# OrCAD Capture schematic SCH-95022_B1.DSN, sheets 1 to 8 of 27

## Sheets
1 Page01 COVER: title: FRDM-IMX8MPLUS; rev: B1; note: SCH-95022 PDF: SPF-95022
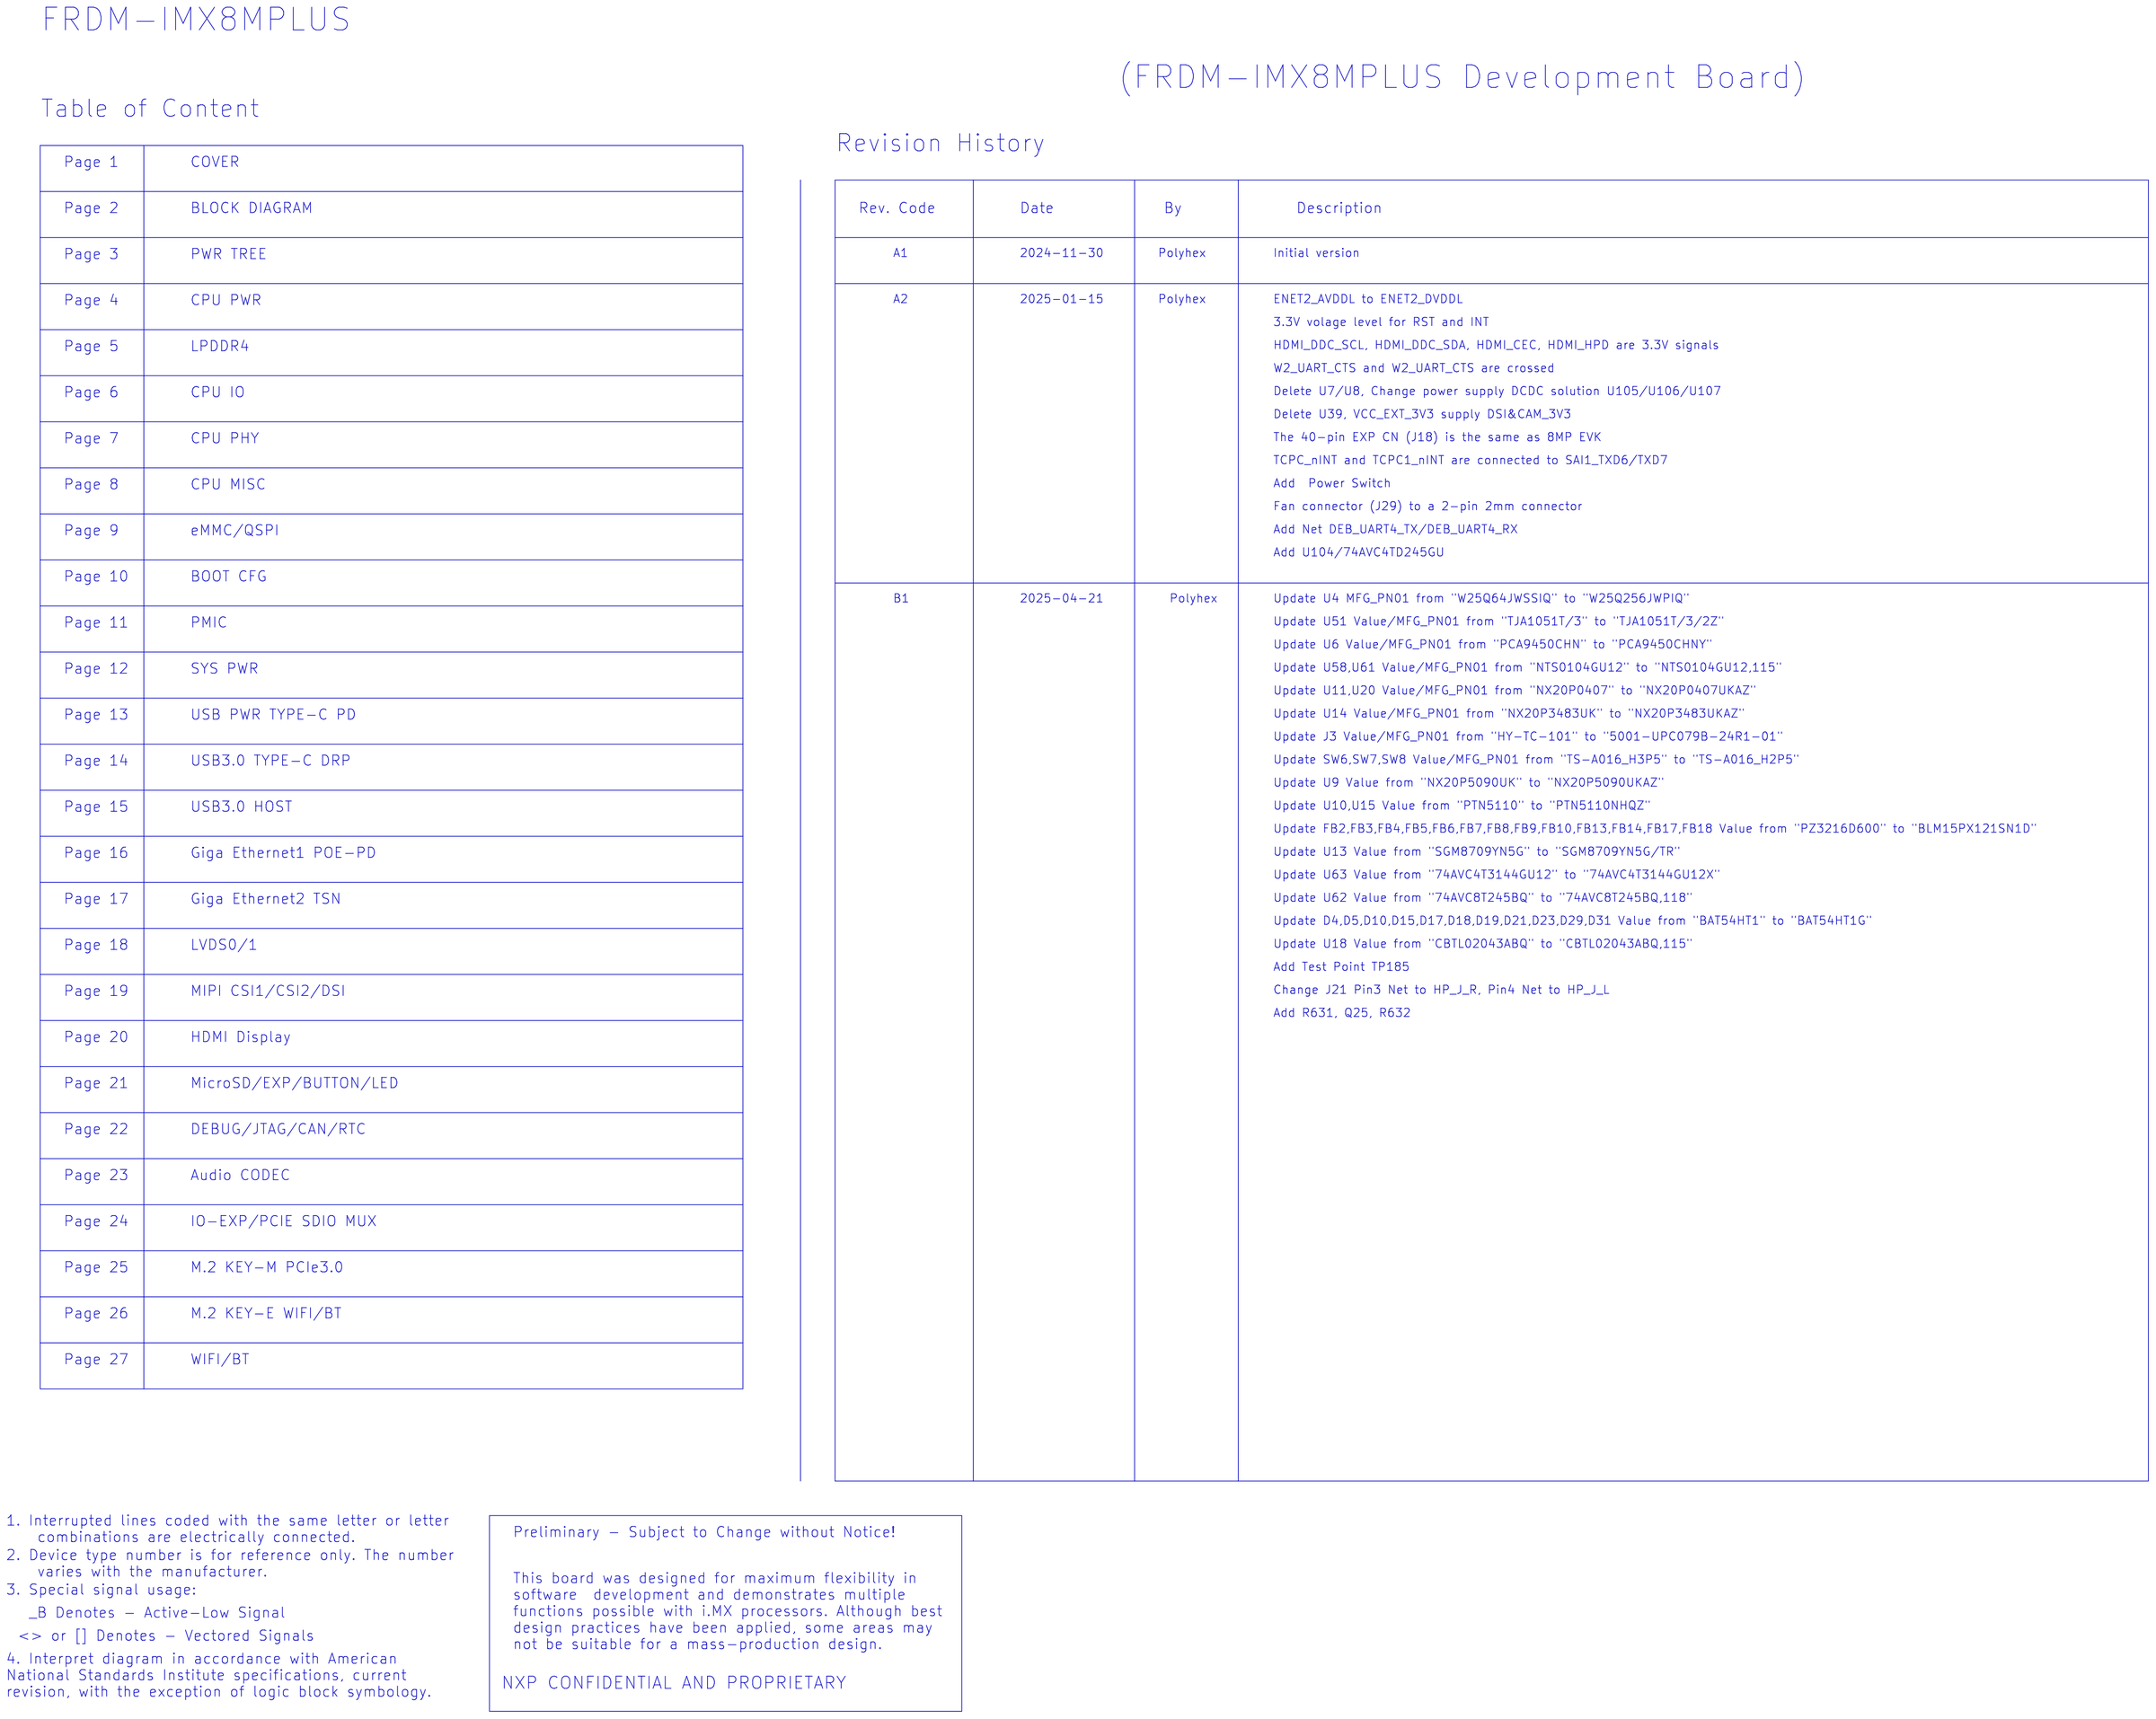
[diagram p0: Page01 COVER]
2 Page02 BLOCK DIAGRAM
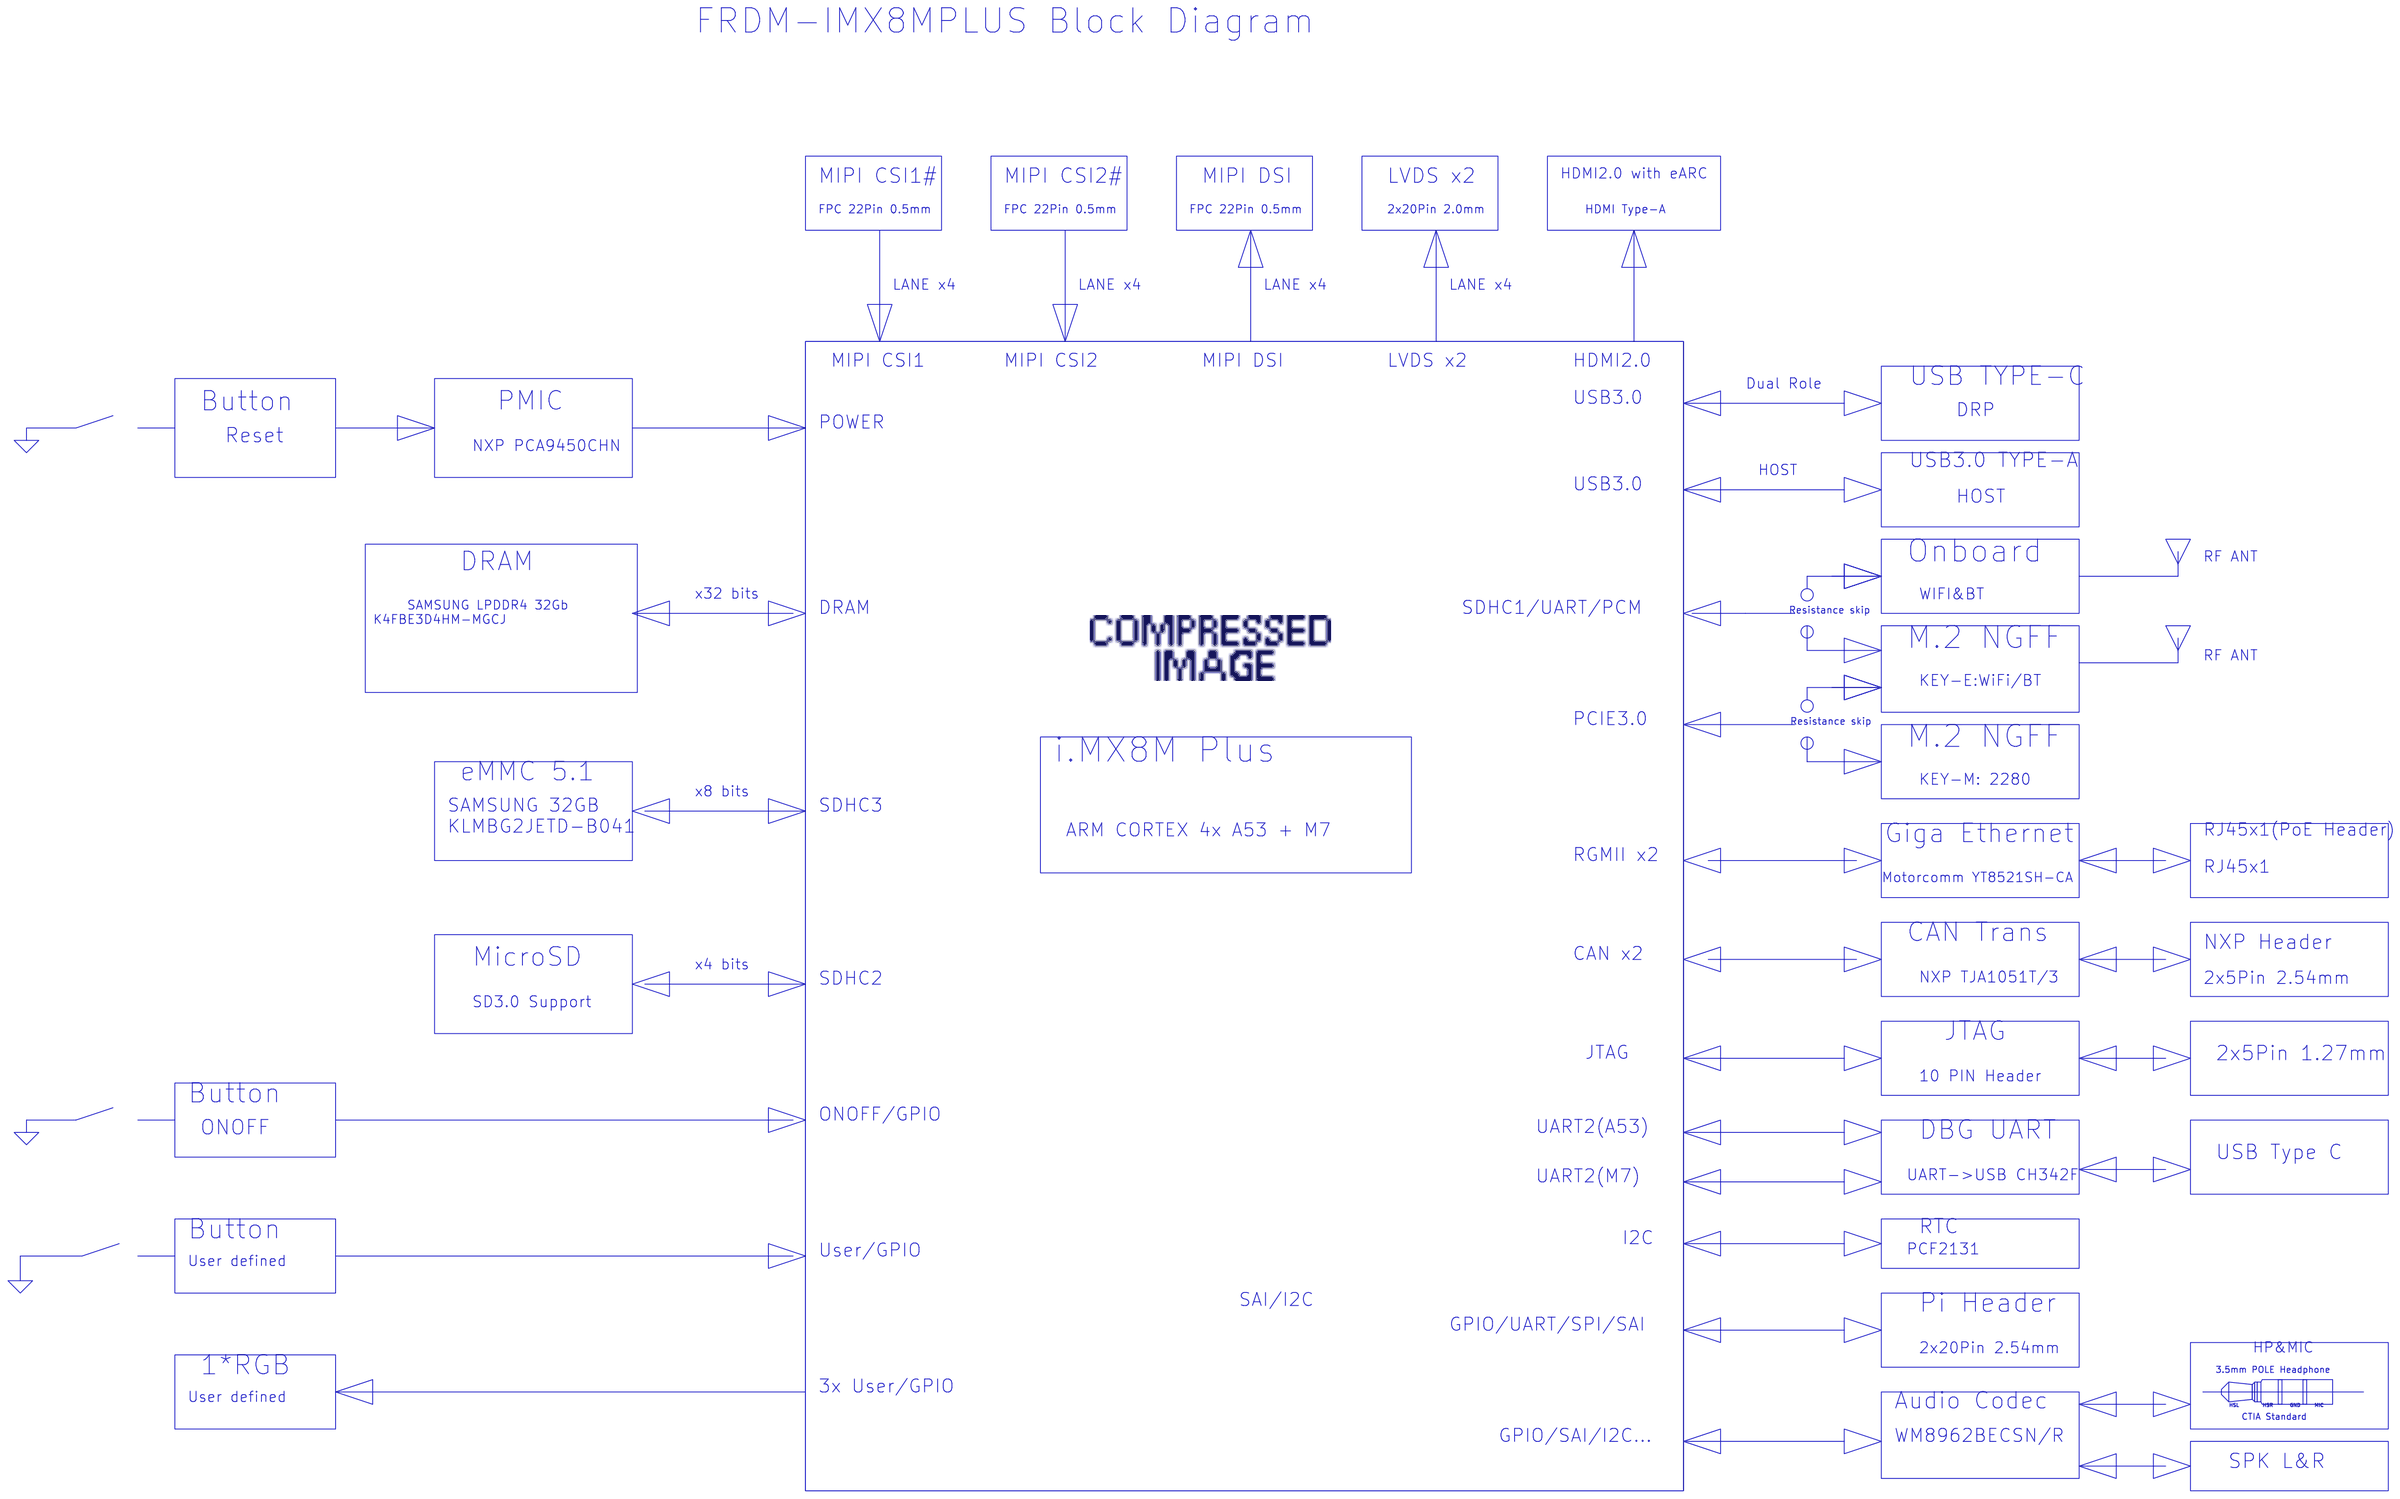
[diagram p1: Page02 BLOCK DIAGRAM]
3 Page03 PWR TREE
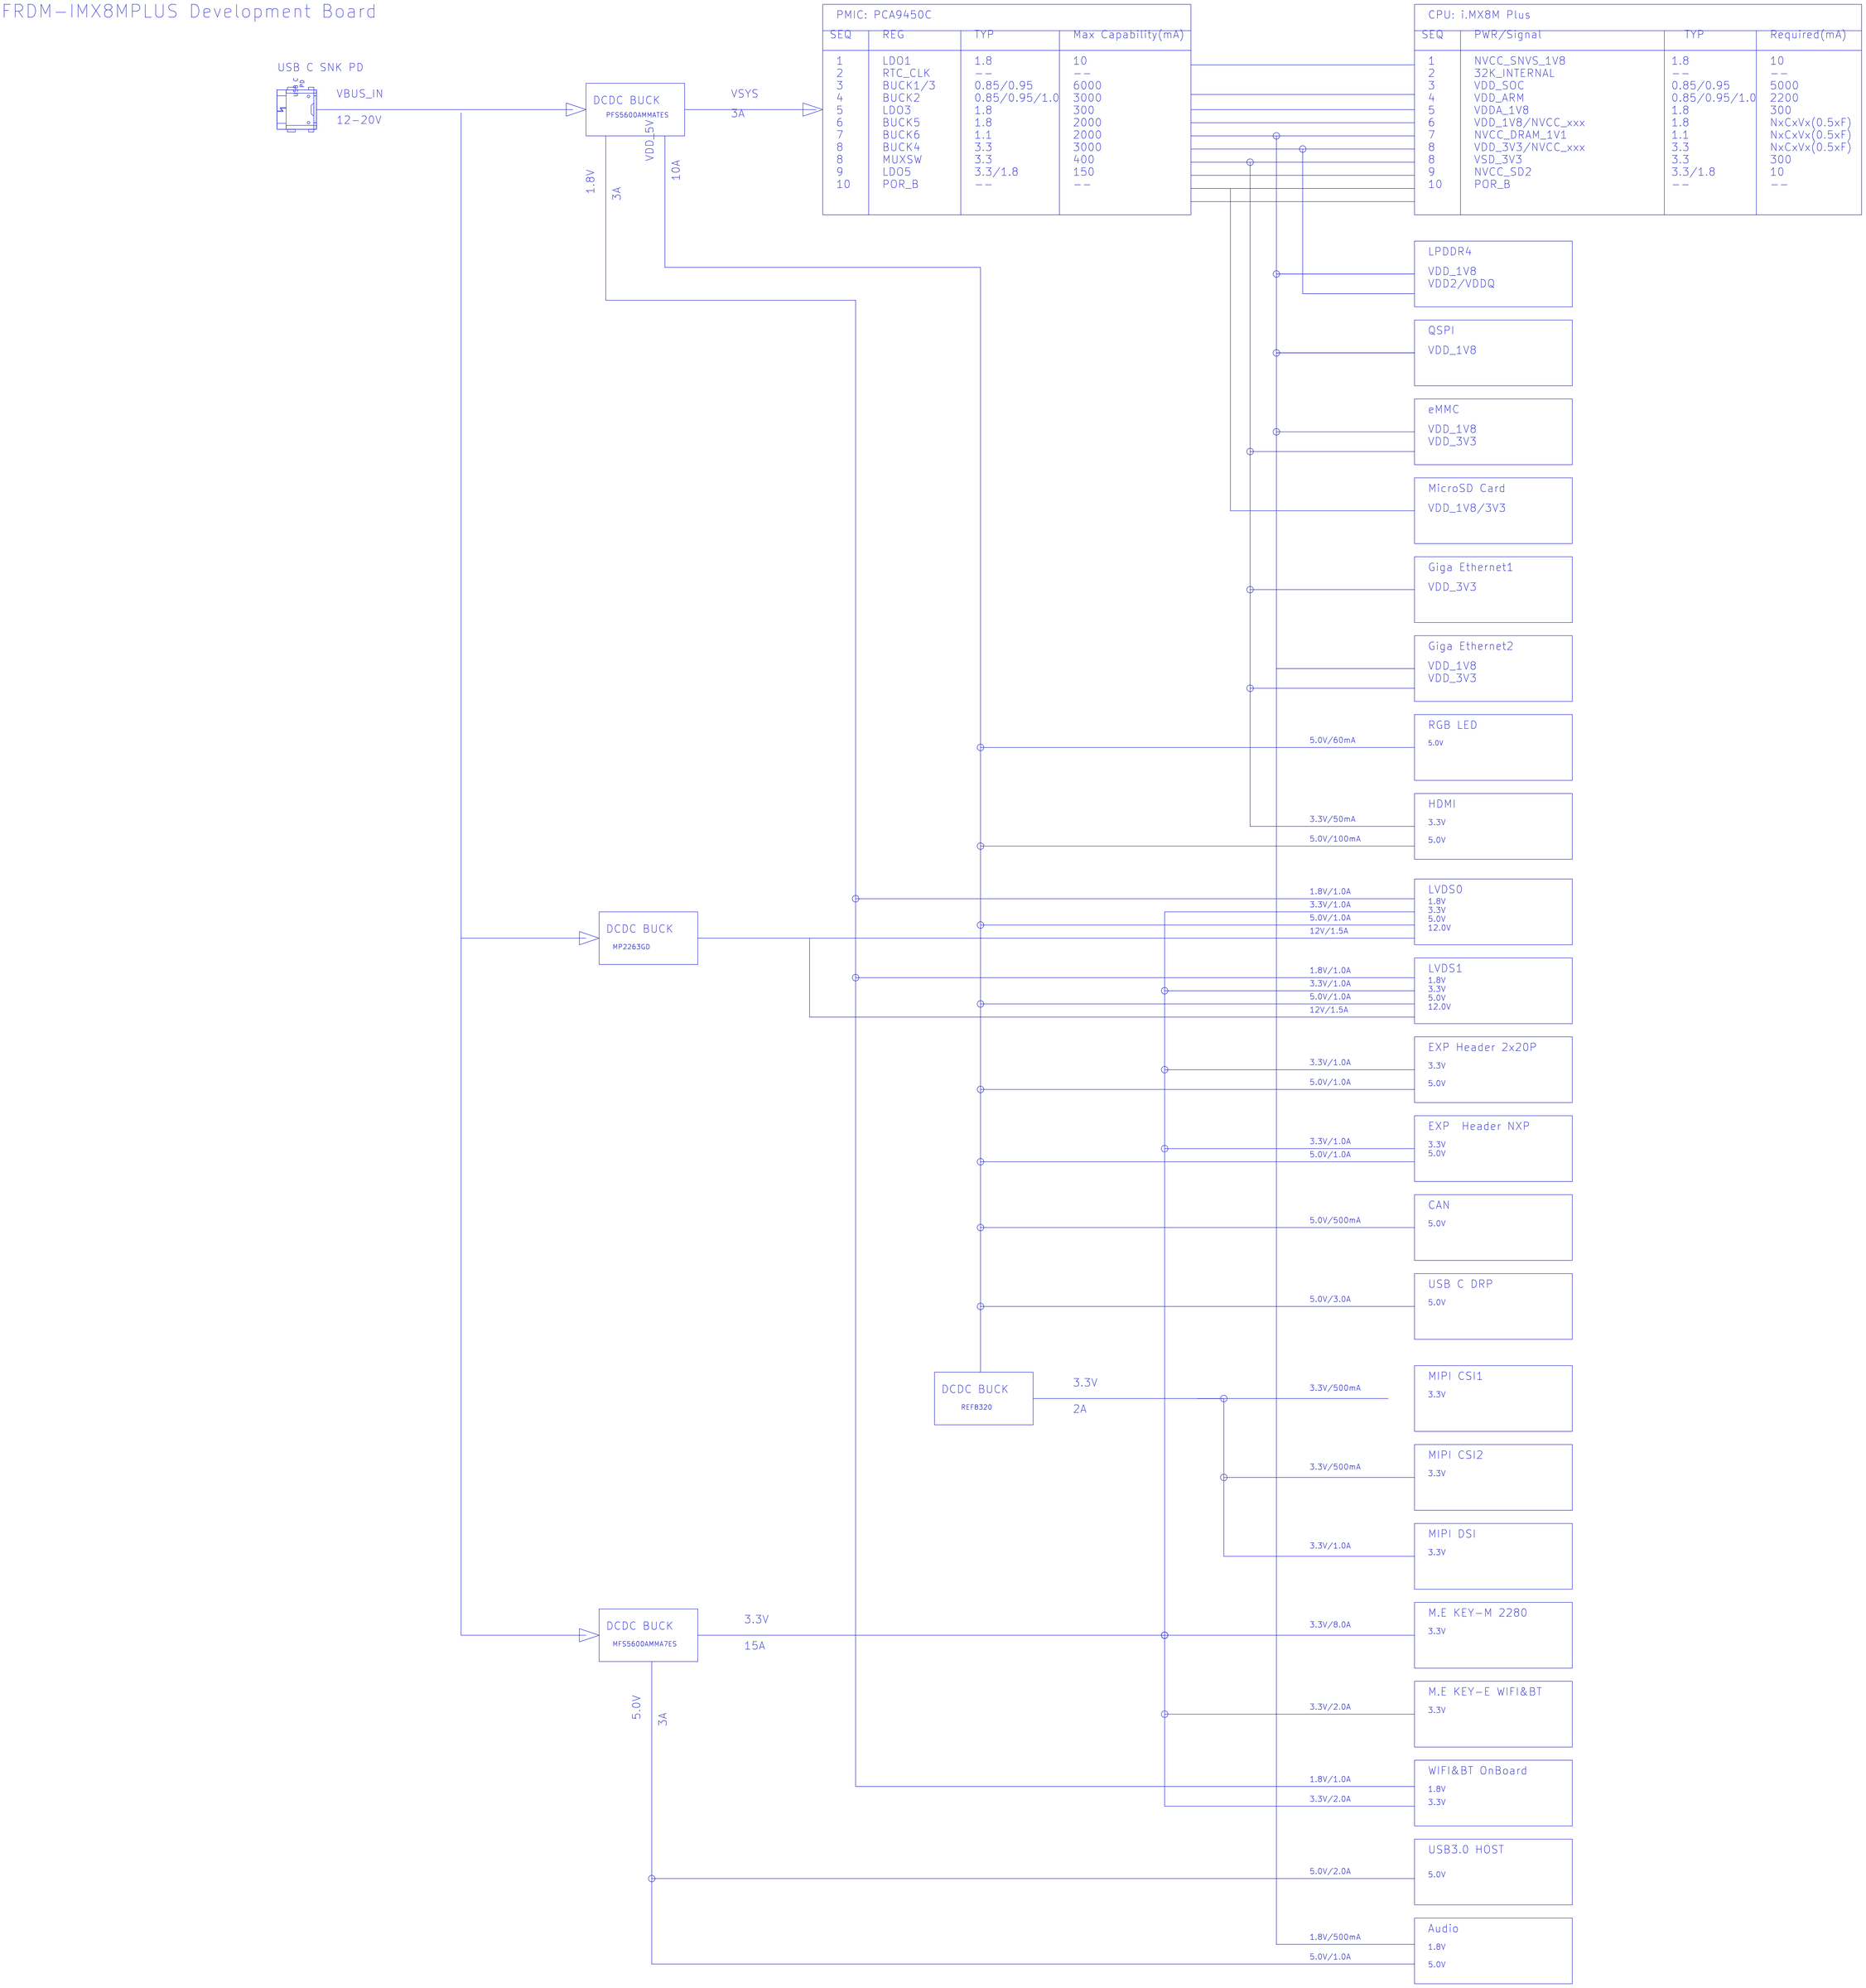
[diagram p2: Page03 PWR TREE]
4 Page04 CPU PWR: size C
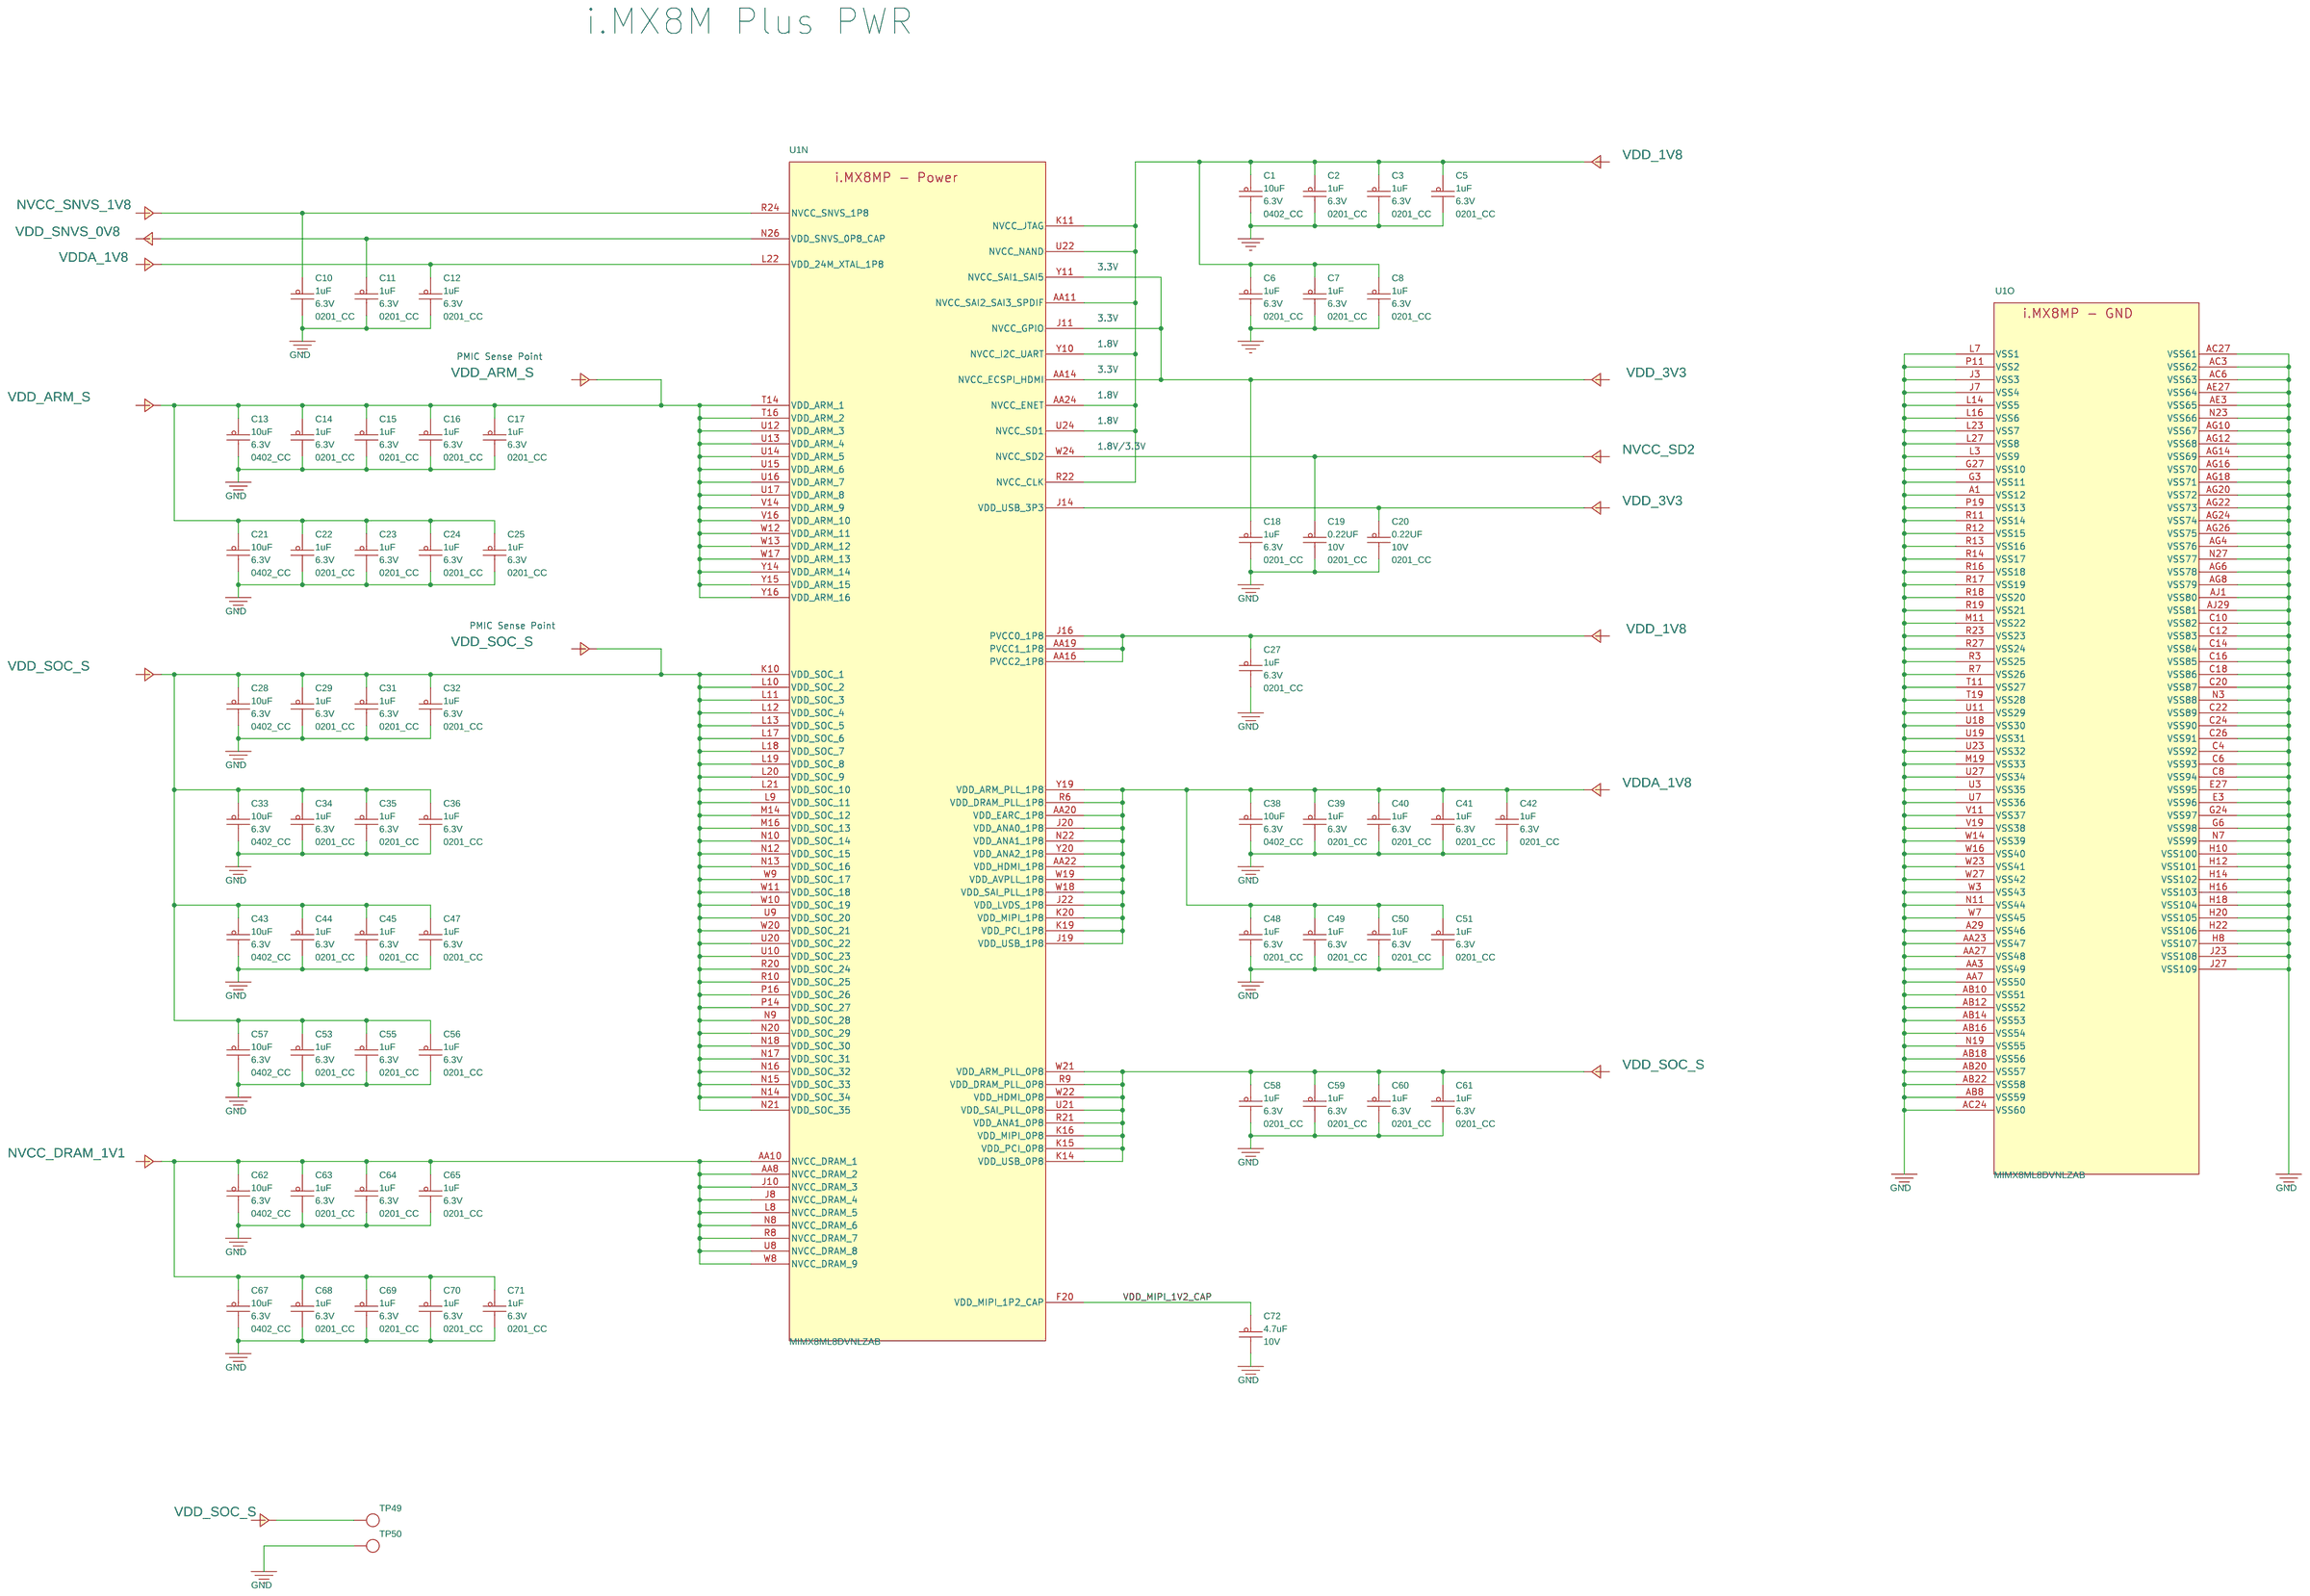
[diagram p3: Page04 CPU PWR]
5 Page05 LPDDR4: size C
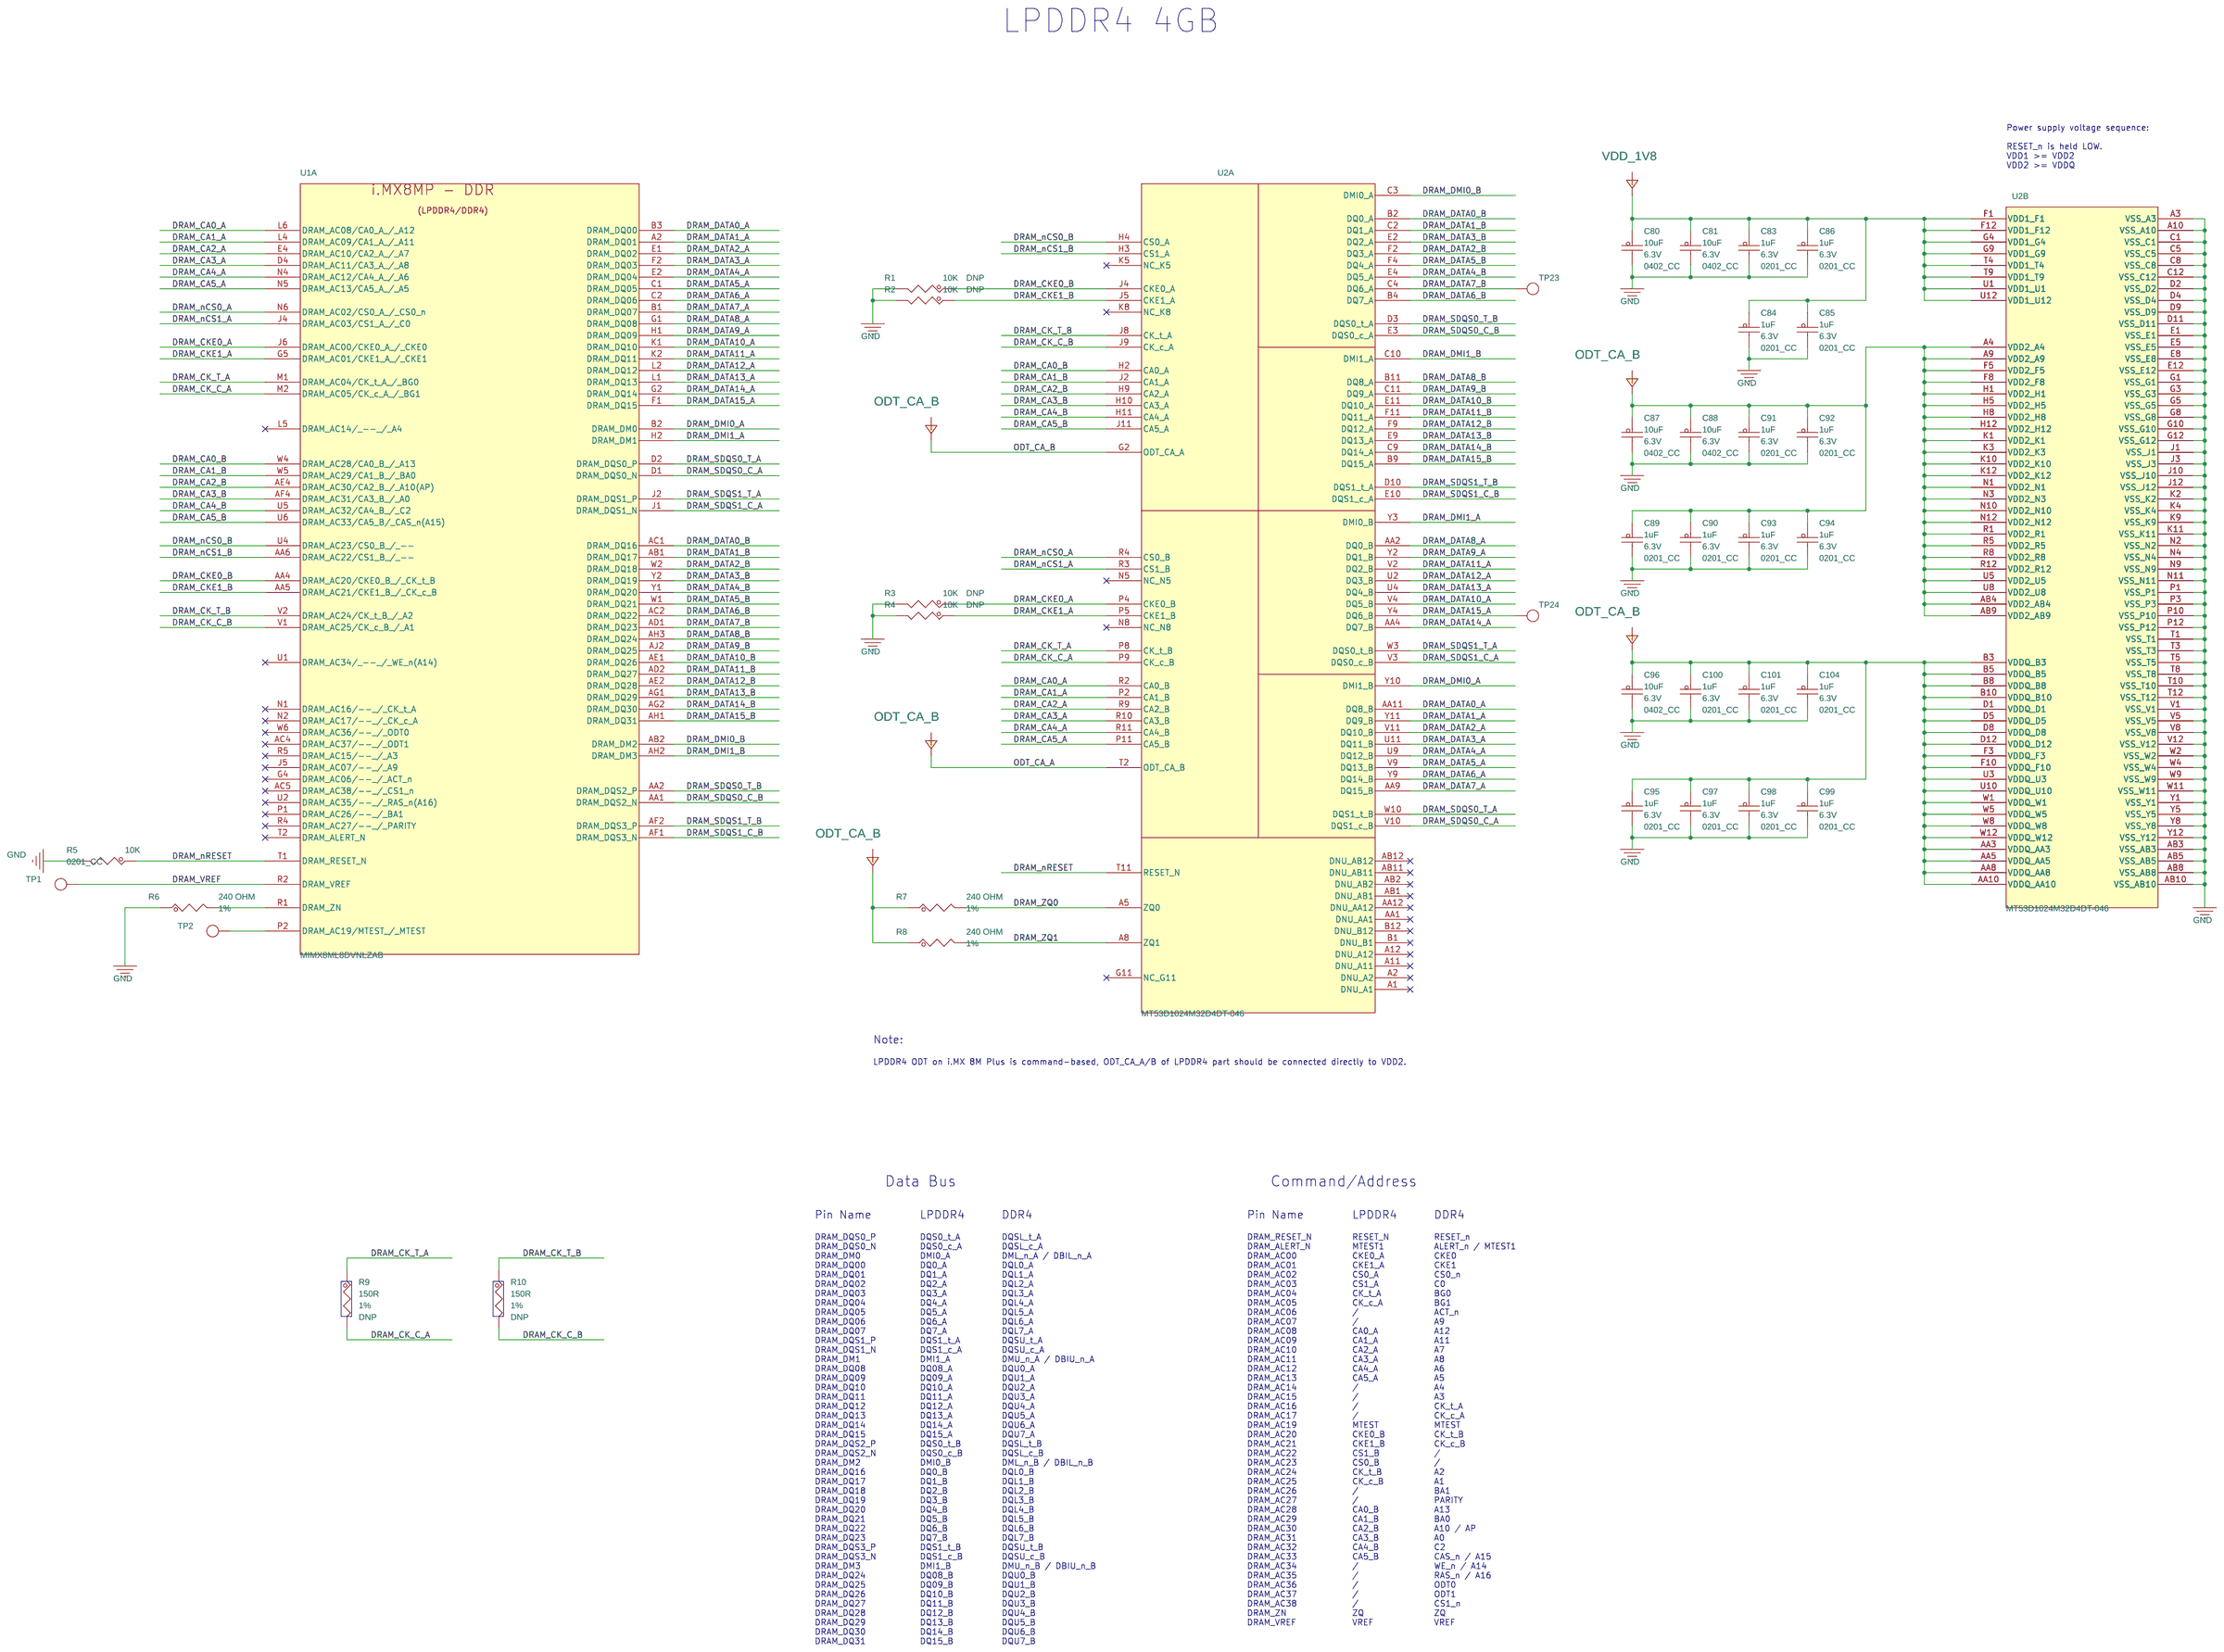
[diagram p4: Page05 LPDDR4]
6 Page06 CPU IO: size C
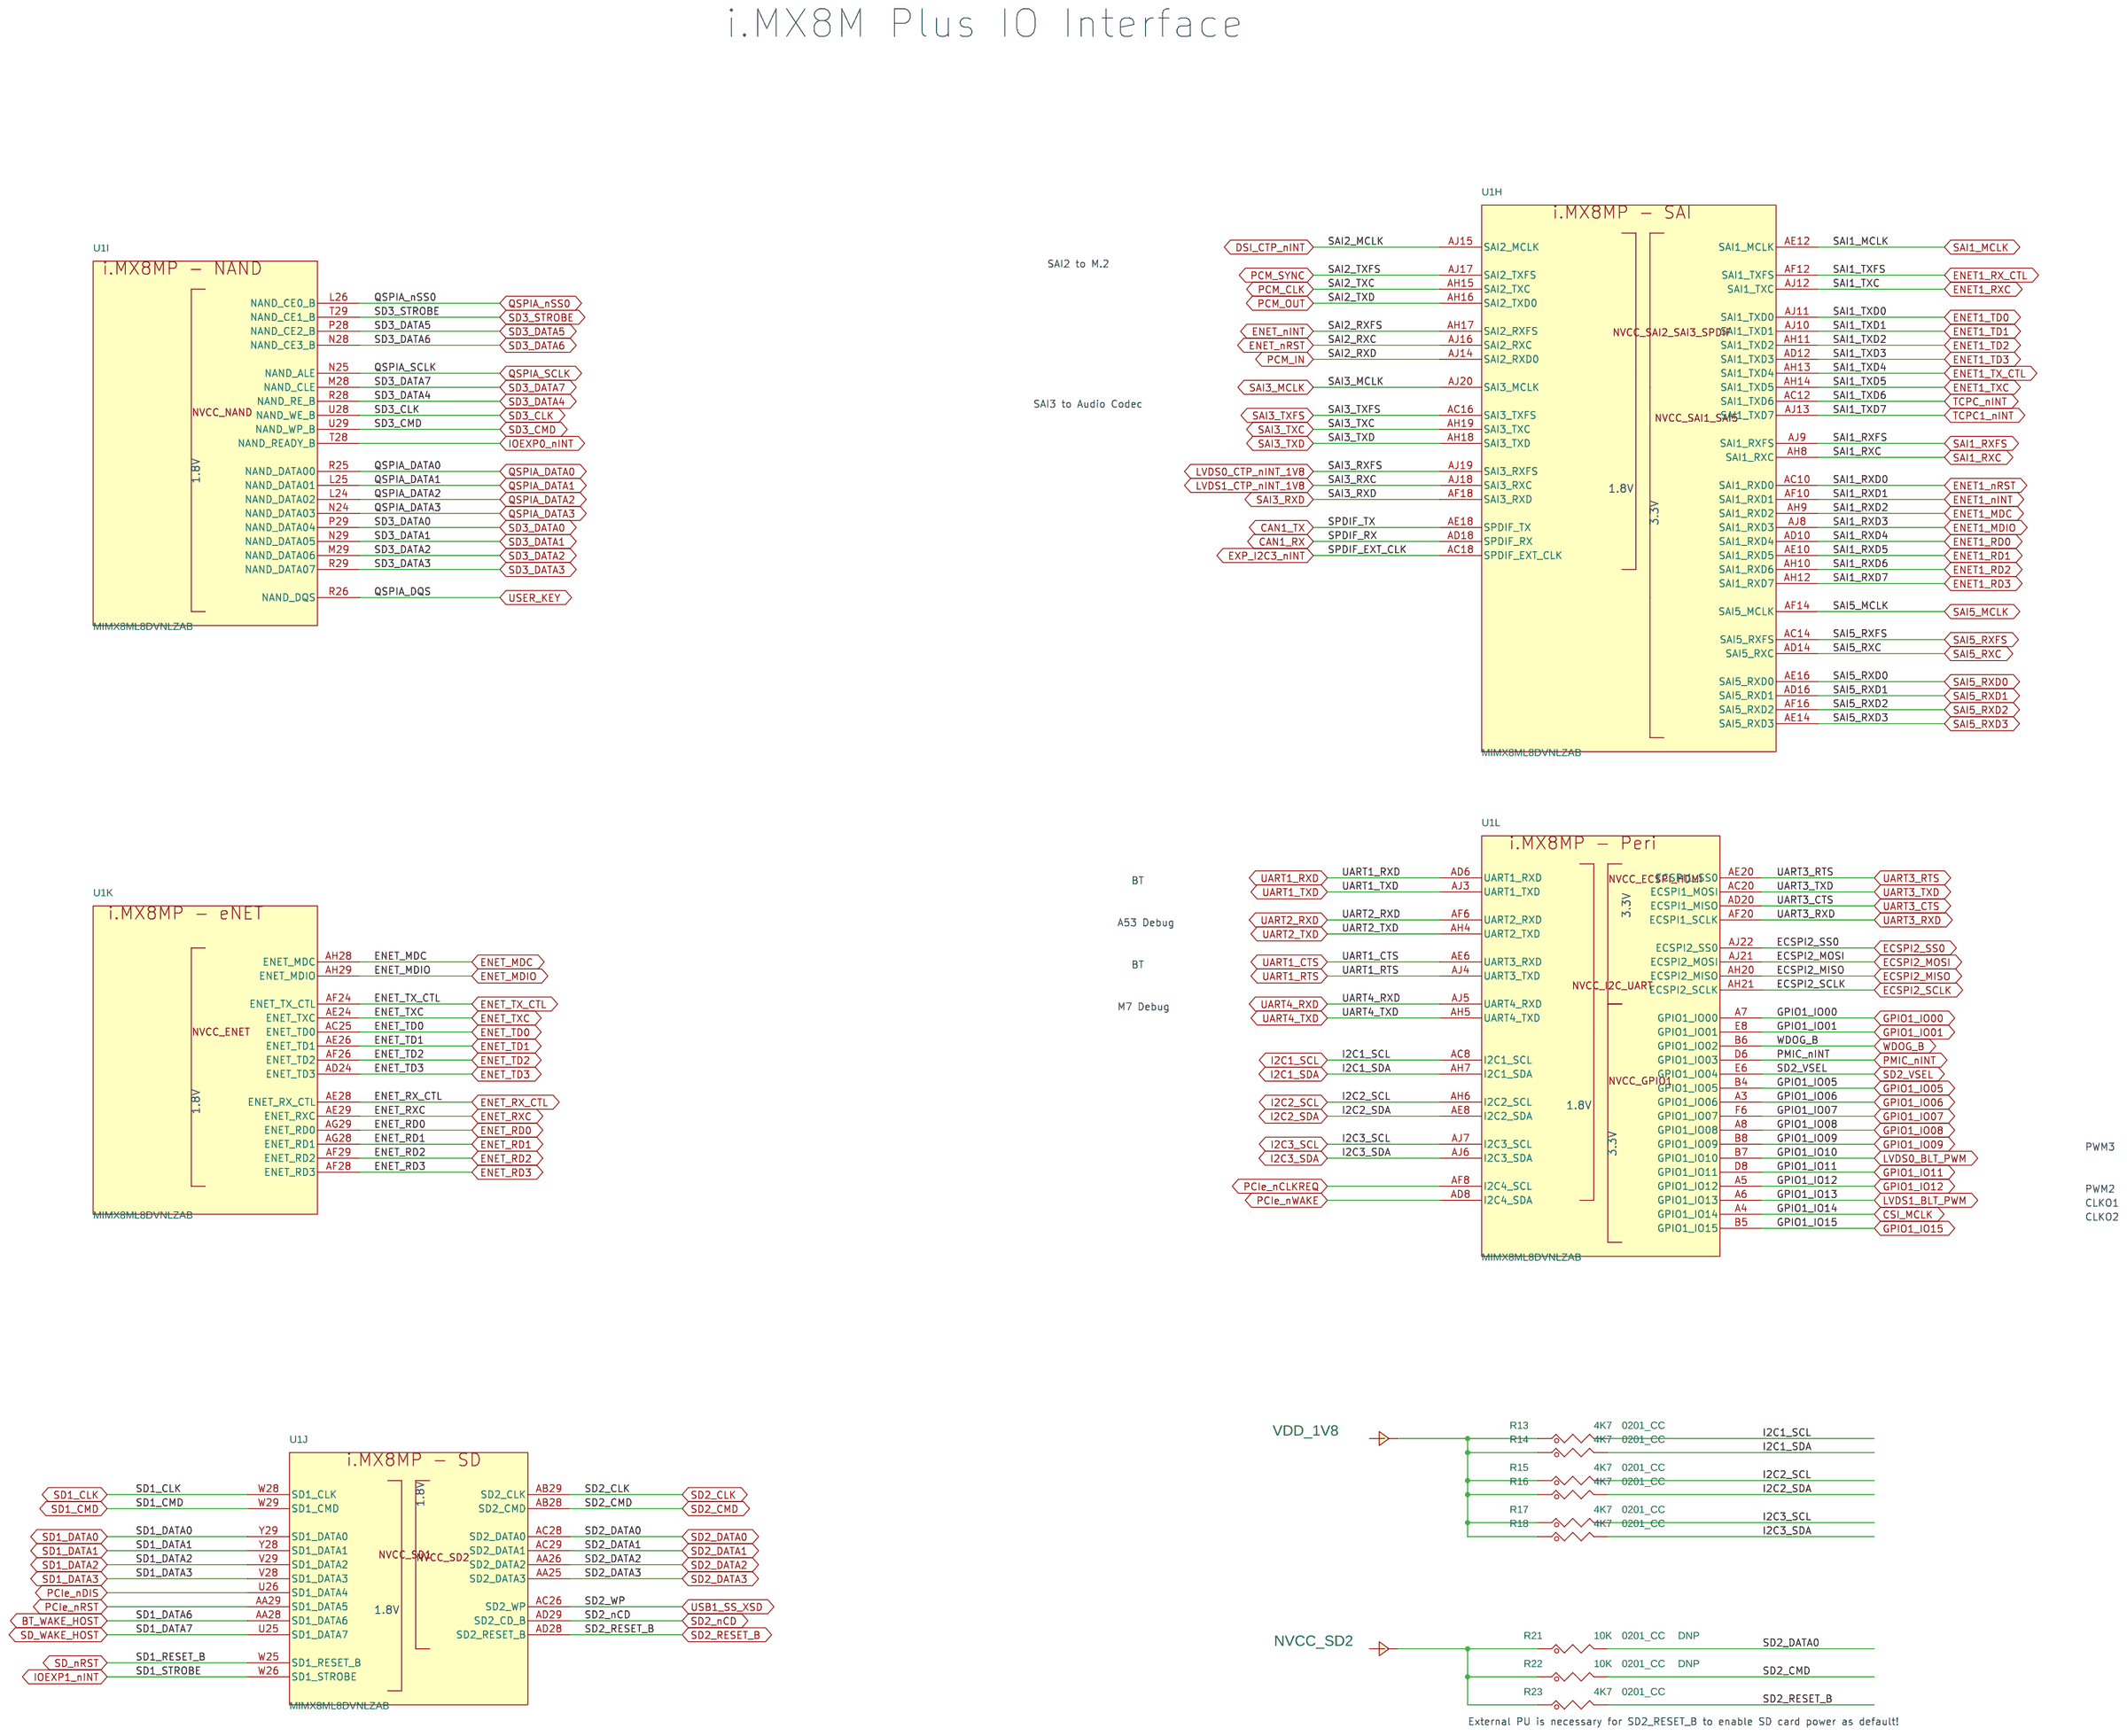
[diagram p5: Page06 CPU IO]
7 Page07 CPU PHY: size C
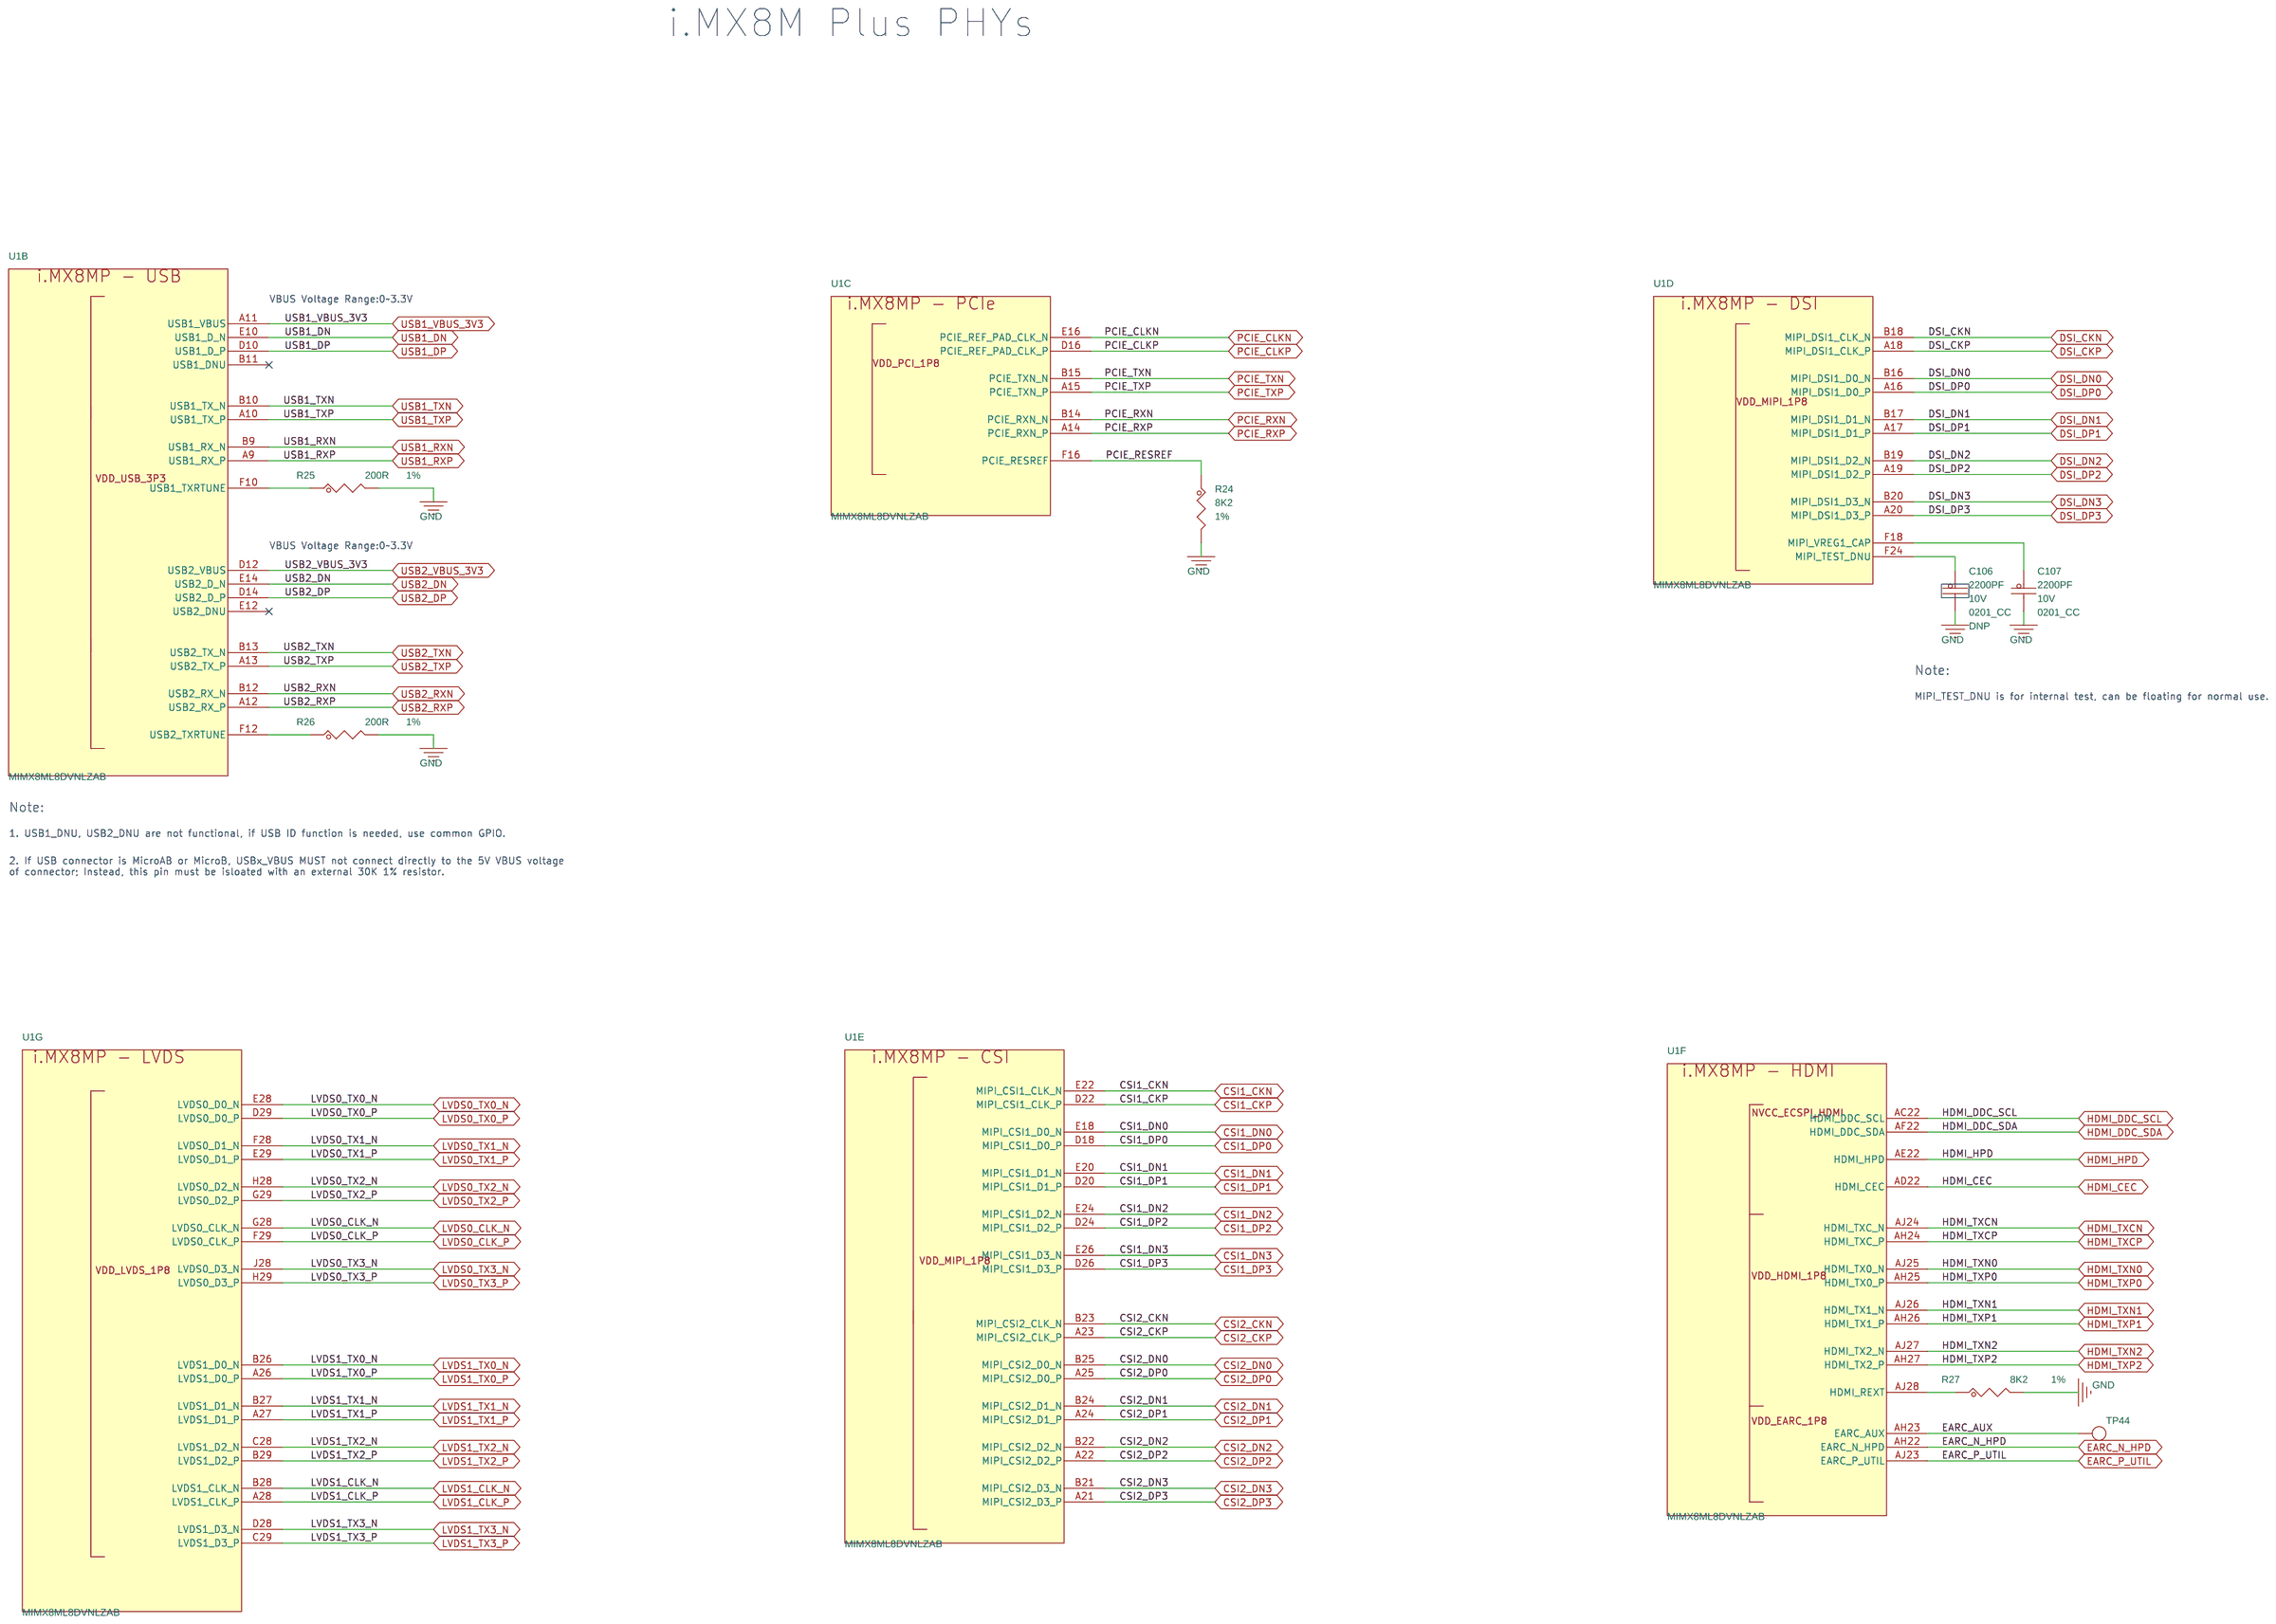
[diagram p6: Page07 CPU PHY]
8 Page08 CPU MISC: size A4
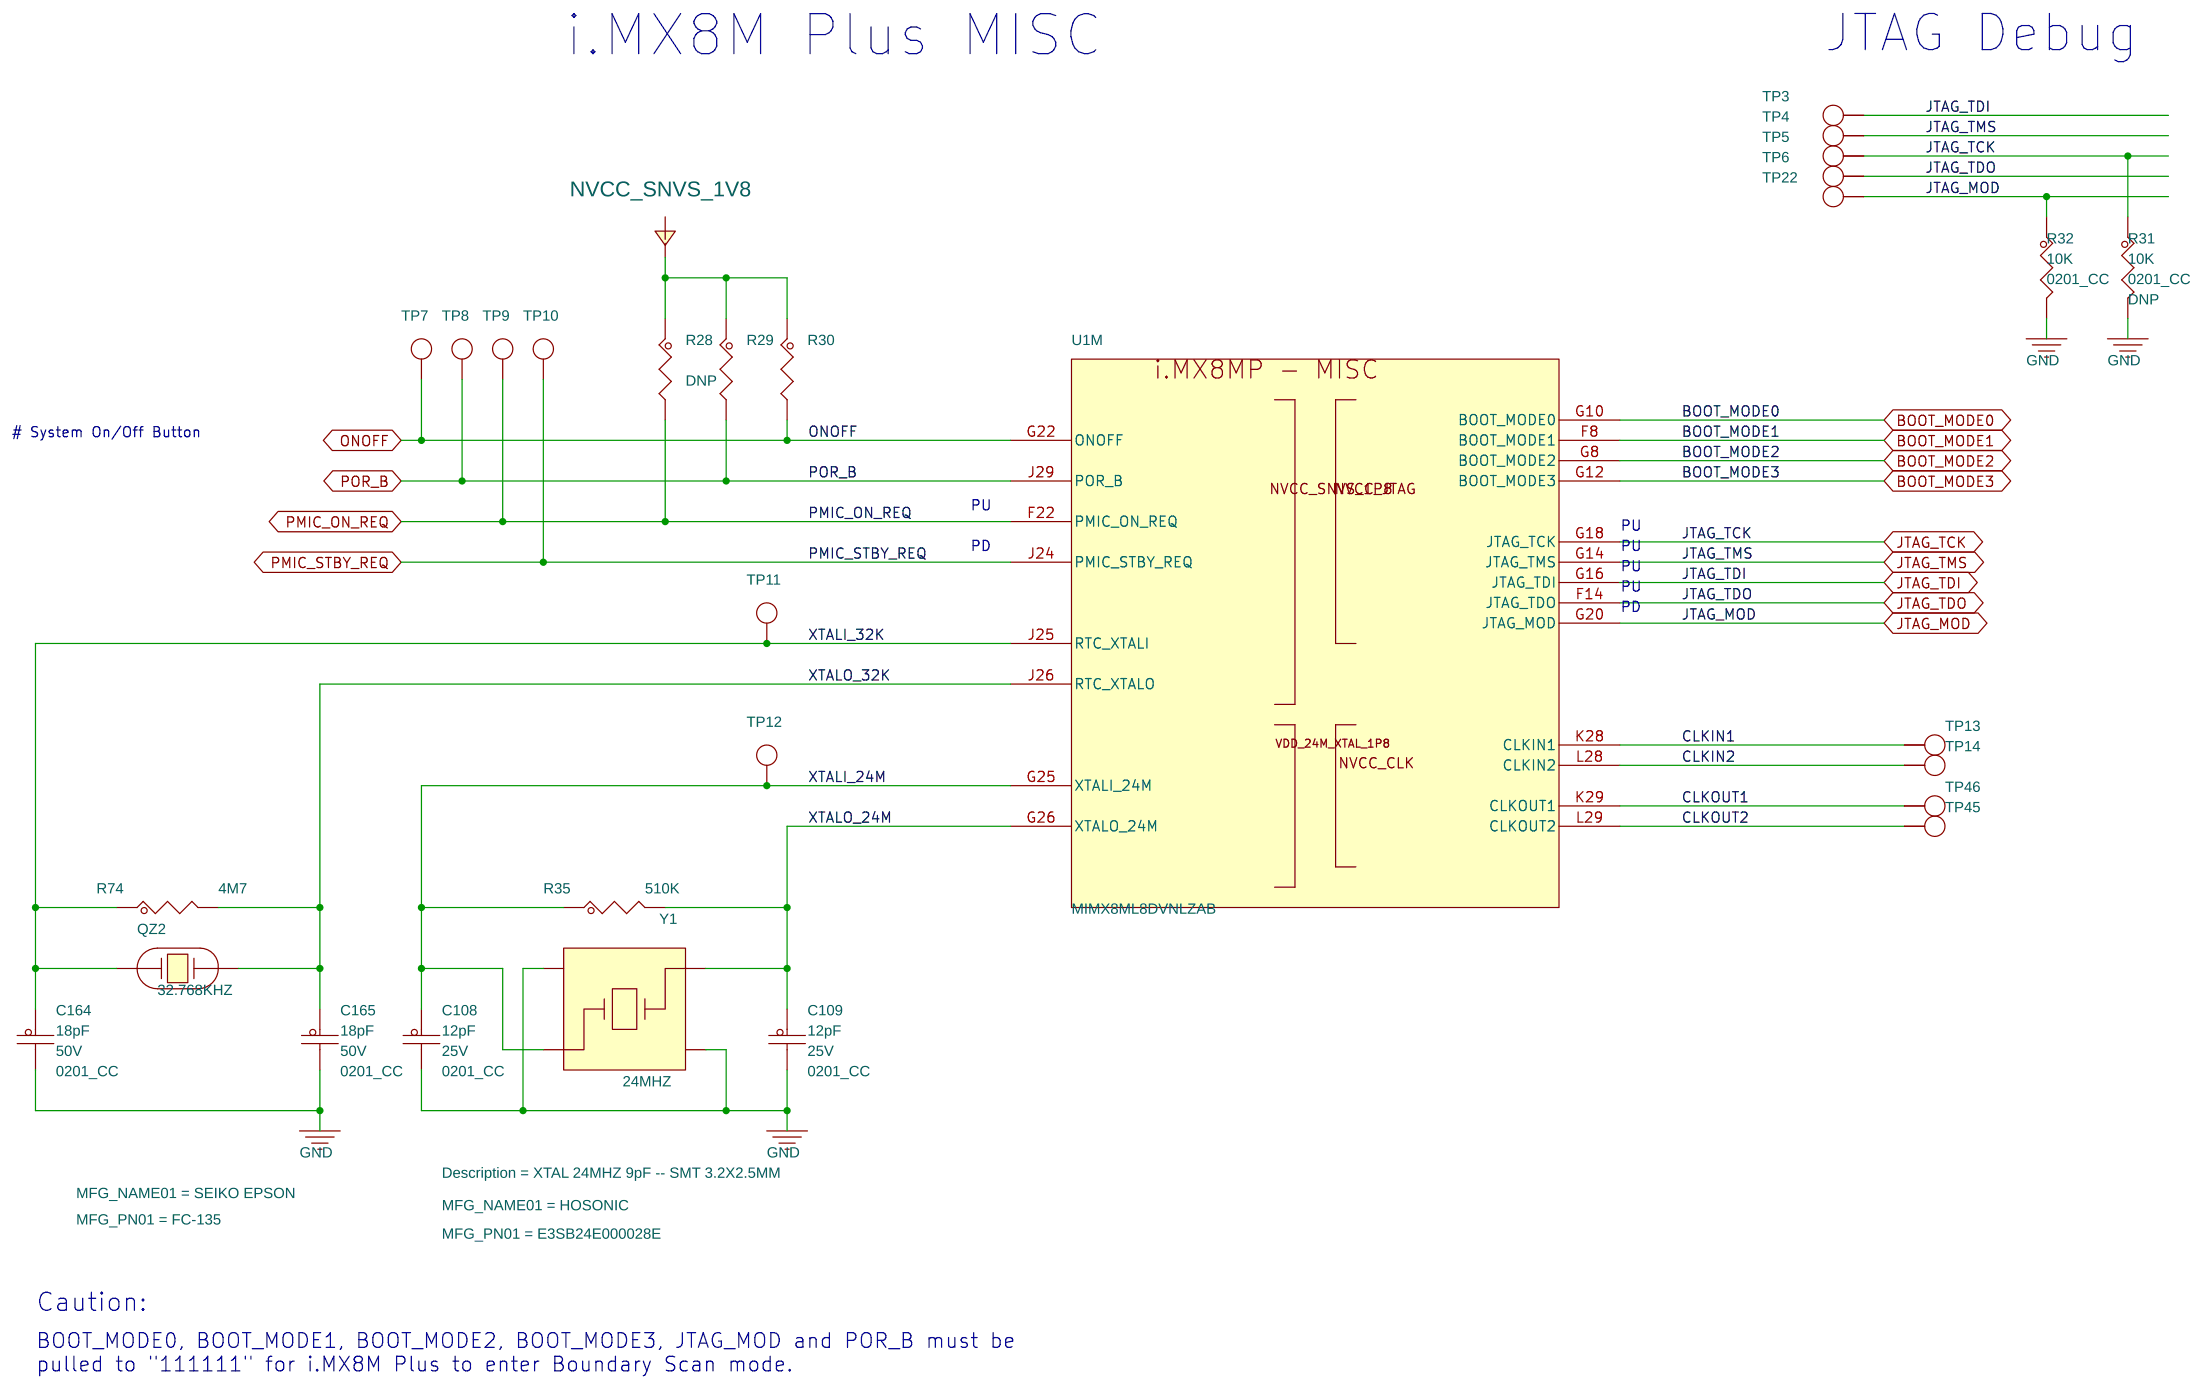
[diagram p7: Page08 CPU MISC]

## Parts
sheet Page04 CPU PWR
C1  10uF  [0402_CC]
C2  1uF  [0201_CC]
C3  1uF  [0201_CC]
C5  1uF  [0201_CC]
C6  1uF  [0201_CC]
C7  1uF  [0201_CC]
C8  1uF  [0201_CC]
C10  1uF  [0201_CC]
C11  1uF  [0201_CC]
C12  1uF  [0201_CC]
C13  10uF  [0402_CC]
C14  1uF  [0201_CC]
C15  1uF  [0201_CC]
C16  1uF  [0201_CC]
C17  1uF  [0201_CC]
C18  1uF  [0201_CC]
C19  0.22UF  [0201_CC]
C20  0.22UF  [0201_CC]
C21  10uF  [0402_CC]
C22  1uF  [0201_CC]
C23  1uF  [0201_CC]
C24  1uF  [0201_CC]
C25  1uF  [0201_CC]
C27  1uF  [0201_CC]
C28  10uF  [0402_CC]
C29  1uF  [0201_CC]
C31  1uF  [0201_CC]
C32  1uF  [0201_CC]
C33  10uF  [0402_CC]
C34  1uF  [0201_CC]
C35  1uF  [0201_CC]
C36  1uF  [0201_CC]
C38  10uF  [0402_CC]
C39  1uF  [0201_CC]
C40  1uF  [0201_CC]
C41  1uF  [0201_CC]
C42  1uF  [0201_CC]
C43  10uF  [0402_CC]
C44  1uF  [0201_CC]
C45  1uF  [0201_CC]
C47  1uF  [0201_CC]
C48  1uF  [0201_CC]
C49  1uF  [0201_CC]
C50  1uF  [0201_CC]
C51  1uF  [0201_CC]
C53  1uF  [0201_CC]
C55  1uF  [0201_CC]
C56  1uF  [0201_CC]
C57  10uF  [0402_CC]
C58  1uF  [0201_CC]
C59  1uF  [0201_CC]
C60  1uF  [0201_CC]
C61  1uF  [0201_CC]
C62  10uF  [0402_CC]
C63  1uF  [0201_CC]
C64  1uF  [0201_CC]
C65  1uF  [0201_CC]
C67  10uF  [0402_CC]
C68  1uF  [0201_CC]
C69  1uF  [0201_CC]
C70  1uF  [0201_CC]
C71  1uF  [0201_CC]
C72  4.7uF  [0402_CC]
TP49  TPAD_020  [tpad_020]
TP50  TPAD_015  [TPAD_015]
sheet Page05 LPDDR4
C80  10uF  [0402_CC]
C81  10uF  [0402_CC]
C83  1uF  [0201_CC]
C84  1uF  [0201_CC]
C85  1uF  [0201_CC]
C86  1uF  [0201_CC]
C87  10uF  [0402_CC]
C88  10uF  [0402_CC]
C89  1uF  [0201_CC]
C90  1uF  [0201_CC]
C91  1uF  [0201_CC]
C92  1uF  [0201_CC]
C93  1uF  [0201_CC]
C94  1uF  [0201_CC]
C95  1uF  [0201_CC]
C96  10uF  [0402_CC]
C97  1uF  [0201_CC]
C98  1uF  [0201_CC]
C99  1uF  [0201_CC]
C100  1uF  [0201_CC]
C101  1uF  [0201_CC]
C104  1uF  [0201_CC]
R1  10K  [0402_CC]
R2  10K  [0402_CC]
R3  10K  [0402_CC]
R4  10K  [0402_CC]
R5  10K  [0201_CC]
R6  240 OHM  [0201_CC]
R7  240 OHM  [0201_CC]
R8  240 OHM  [0201_CC]
R9  150R  [0402_CC]
R10  150R  [0402_CC]
TP1  TPAD_015  [TPAD_015]
TP2  TPAD_015  [TPAD_015]
TP23  TPAD_020  [tpad_020]
TP24  TPAD_020  [tpad_020]
U1  MIMX8ML8DVNLZAB  [bga548_0p5_15x15mm]  (sections A,B,C,D,E,F,G,H,I,J,K,L,M,N,O)
U2  MT53D1024M32D4DT-046  [bga200_0p65x0p8_10p1x14p6]  (sections A,B)
sheet Page06 CPU IO
R13  4K7  [0201_CC]
R14  4K7  [0201_CC]
R15  4K7  [0201_CC]
R16  4K7  [0201_CC]
R17  4K7  [0201_CC]
R18  4K7  [0201_CC]
R21  10K  [0201_CC]
R22  10K  [0201_CC]
R23  4K7  [0201_CC]
sheet Page07 CPU PHY
C106  2200PF  [0201_CC]
C107  2200PF  [0201_CC]
R24  8K2  [0201_CC]
R25  200R  [0201_CC]
R26  200R  [0201_CC]
R27  8K2  [0201_CC]
TP44  TPAD_020  [tpad_020]
sheet Page08 CPU MISC
C108  12pF  [0201_CC]
C109  12pF  [0201_CC]
C164  18pF  [0201_CC]
C165  18pF  [0201_CC]
QZ2  32.768KHZ  [XTAL2-3P2X1P5-SM]
R28  100K  [0402_CC]
R29  100K  [0402_CC]
R30  100K  [0402_CC]
R31  10K  [0201_CC]
R32  10K  [0201_CC]
R35  510K  [0402_CC]
R74  4M7  [0201_CC]
TP3  TPAD_020  [tpad_020]
TP4  TPAD_020  [tpad_020]
TP5  TPAD_020  [tpad_020]
TP6  TPAD_020  [tpad_020]
TP7  TPAD_015  [TPAD_015]
TP8  TPAD_015  [TPAD_015]
TP9  TPAD_015  [TPAD_015]
TP10  TPAD_015  [TPAD_015]
TP11  TPAD_015  [TPAD_015]
TP12  TPAD_015  [TPAD_015]
TP13  TPAD_020  [tpad_020]
TP14  TPAD_020  [tpad_020]
TP22  TPAD_020  [tpad_020]
TP45  TPAD_020  [tpad_020]
TP46  TPAD_020  [tpad_020]
Y1  24MHZ  [xtlosc4_3p2x2p5mm_sm]

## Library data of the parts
C1 C13 C21 C28 C33 C38 C43 C57 C62 C67 C80 C81 C87 C88 C96 = CAP_NP: CAP CER 10UF 6.3V 20% X5R 0402; AGILE_PN: 150-79163; CAD_APPROVED: Yes; FPLIST: CC0402_25,CC0402_HD,0402_CC; HEIGHT: 0.65 MM; MFG_NAME01: SAMSUNG; MFG_PN01: CL05A106MQ5NUNC; Polyhex_Number: PD.005.0031; ROHS: Yes; Tolerance: 20%; VOLTAGE: 6.3V
C2 C3 C5-C8 C10-C12 C14-C18 C22-C25 C27 C29 C31 C32 C34-C36 C39-C42 C44 C45 C47-C51 C53 C55 C56 C58-C61 C63-C65 C68-C71 C83-C86 C89-C95 C97-C101 C104 = CAP_NP: CAP CER 1uF 6.3V 10% X5R 0201; AGILE_PN: 150-79407; CAD_APPROVED: Yes; FPLIST: CC0201,CC0201_HD,0201_CC,0201_CC_012SM_NSP; HEIGHT: 0.35MM; MFG_NAME01: SAMSUNG; MFG_PN01: CL03A105KQ3CSNH; Package Size: 0201; Package Type: 7” reel; Polyhex_Number: PD.005.0030; ROHS: Yes; Tolerance: 10%; VOLTAGE: 6.3V
C19 C20 = CAP_NP: CAP CER 0.22UF 10V 20% X5R 0201; AGILE_PN: 150-78815; CAD_APPROVED: Yes; FPLIST: CC0201,CC0201_HD,0201_CC; HEIGHT: 0.33MM; MFG_NAME01: SAMSUNG; MFG_PN01: CL03A224KP3NNNH; Polyhex_Number: PD.005.0029; ROHS: Yes; Tolerance: 20%; VOLTAGE: 10V
C72 = CAP_NP: CAP CER 4.7uF 10V 10% X5R 0402; CAD_APPROVED: Yes; HEIGHT: 0.95MM; MFG_NAME01: SAMSUNG; MFG_PN01: CL05A475KP5NRNC; Polyhex_Number: PD.005.0058; ROHS: Yes; Temp Range: -55°C to + 85°C; Tolerance: 10%; VOLTAGE: 10V
TP3-TP6 TP13 TP14 TP22-TP24 TP44-TP46 TP49 = TESTLOOP: TEST POINT PAD 0.5MM DIA SMT, NO PART TO ORDER; AGILE_PN: 211-77484; ASSY_OPT: DNP; CAD_APPROVED: Yes; HEIGHT: 0.1MM; MFG_NAME01: NOT A COMPONENT; MFG_PN01: NOT A COMPONENT; Polyhex_Number: TEST POINT; ROHS: Yes
TP1 TP2 TP7-TP12 TP50 = TestLoop: TEST POINT PAD 15MIL DIA SMT, NO PART TO ORDER; AGILE_PN: 211-76645; ASSY_OPT: DNP; CAD_APPROVED: Yes; HEIGHT: 0.1MM; MFG_NAME01: NOT A COMPONENT; MFG_PN01: NOT A COMPONENT; Polyhex_Number: TEST POINT; ROHS: Yes
R1-R4 = RES: RES MF 10K 1/16W 5% 0402; AGILE_PN: 470-75557; ASSY_OPT: DNP; CAD_APPROVED: Yes; FPLIST: RC0402_25,RC0402_HD,0402_CC; HEIGHT: 0.4 MM; MFG_NAME01: YAGEO; MFG_PN01: RC0402JR-0710KL; Polyhex_Number: PD.004.0010; ROHS: Yes; Tolerance: 5%; VOLTAGE: 50V
R5 R32 = RES: RES MF 10K 1/20W 5% 0201; CAD_APPROVED: Yes; HEIGHT: 0.23mm; MFG_NAME01: YAGEO; MFG_PN01: RC0201JR-0710KL; Polyhex_Number: PD.004.0069; ROHS: Yes; Tolerance: 5%; VOLTAGE: 25V
R6-R8 = RES: RES MF 240 OHM 1/20W 1% 0201; AGILE_PN: 470-81317; CAD_APPROVED: Yes; FPLIST: CC0201,CC0201_HD,0201_CC; HEIGHT: 0.26MM; MFG_NAME01: YAGEO; MFG_PN01: RC0201FR-07240RL; Polyhex_Number: PD.004.0070; ROHS: Yes; Temp Range: -55°C ~ 125°C; Temp_Range: -55°C ~ 125°C; Tolerance: 1%; VOLTAGE: 25V
R9 R10 = RES: RES MF 150 OHM 1/16W 1% 0402; AGILE_PN: 470-75353; ASSY_OPT: DNP; CAD_APPROVED: Yes; FPLIST: RC0402_25,RC0402_HD,0402_CC; HEIGHT: 0.4MM; MFG_NAME01: YAGEO; MFG_PN01: RC0402FR-07150RL; Polyhex_Number: PD.004.0071; ROHS: Yes; Tolerance: 1%; VOLTAGE: 50V
U1 = MIMX8MP_BGA548: IC CPU QUAD CORTEX A53+M4 1.8GHZ BGA548; AGILE_PN: 330-77126; CAD_APPROVED: Yes; HEIGHT: 2.1MM; MFG_NAME01: NXP SEMICONDUCTORS; Polyhex_Number: PD.008.0111; CLASS: IC; SPLIT_INST: TRUE
U2 = MT53B768M32D4NQ_200P: IC MEM LPDDR4 SDRAM 1G x 32 1.1V VFBGA200; AGILE_PN: TMP-WF-36000; CAD_APPROVED: Yes; HEIGHT: 0.95MM; MFG_NAME01: MICRON; PRE_APN: 334-77850; Polyhex_Number: PD.008.0031; ROHS: Yes; Temp Range: –25°C to +85°C; Temp_Range: –25°C to +85°C; VOLTAGE: 1.1V
R13-R18 R23 = RES: RES MF 4K7 1/20W 5% 0201; AGILE_PN: 470-82323; CAD_APPROVED: Yes; FPLIST: RC0201,0201_CC; HEIGHT: 0.26MM; MFG_NAME01: YAGEO; MFG_PN01: RC0201JR-074K7L; Polyhex_Number: PD.004.0072; ROHS: Yes; Temp Range: -55°C ~ 125°C; Temp_Range: -55°C ~ 125°C; Tolerance: 5%; VOLTAGE: 25V
R21 R22 R31 = RES: RES MF 10K 1/20W 5% 0201; ASSY_OPT: DNP; CAD_APPROVED: Yes; HEIGHT: 0.23mm; MFG_NAME01: YAGEO; MFG_PN01: RC0201JR-0710KL; Polyhex_Number: PD.004.0069; ROHS: Yes; Tolerance: 5%; VOLTAGE: 25V
C106 = CAP_NP: CAP CER 2200PF 10V 10% X7R 0201; AGILE_PN: 150-78660; ASSY_OPT: DNP; CAD_APPROVED: Yes; FPLIST: CC0201,CC0201_HD,0201_CC; HEIGHT: 0.33 MM; MFG_NAME01: SAMSUNG; MFG_PN01: CL03B222KP3NNNH; Polyhex_Number: PD.005.0034; ROHS: Yes; Tolerance: 10%; VOLTAGE: 10V
C107 = CAP_NP: CAP CER 2200PF 10V 10% X7R 0201; AGILE_PN: 150-78660; CAD_APPROVED: Yes; FPLIST: CC0201,CC0201_HD,0201_CC; HEIGHT: 0.33 MM; MFG_NAME01: SAMSUNG; MFG_PN01: CL03B222KP3NNNH; Polyhex_Number: PD.005.0034; ROHS: Yes; Tolerance: 10%; VOLTAGE: 10V
R24 R27 = RES: RES MF 8K2 1/20W 1% 0201; AGILE_PN: 470-82483; CAD_APPROVED: Yes; FPLIST: RC0201,0201_CC; HEIGHT: 0.26MM; MFG_NAME01: YAGEO; MFG_PN01: RC0201FR-078K2L; Package Size: 0201; Package Type: SMD; Polyhex_Number: PD.004.0220; ROHS: Yes; Tolerance: 1%; VOLTAGE: 25V
R25 R26 = RES: RES MF 200 OHM 1/20W 1% 0201; AGILE_PN: 470-82323; CAD_APPROVED: Yes; FPLIST: RC0201,0201_CC; HEIGHT: 0.26MM; MFG_NAME01: YAGEO; MFG_PN01: RC0201FR-07200RL; Polyhex_Number: PD.004.0076; ROHS: Yes; Temp Range: -55°C ~ 125°C; Temp_Range: -55°C ~ 125°C; Tolerance: 1%; VOLTAGE: 25V
C108 C109 = CAP_NP: CAP CER 12PF 25V 5% C0G 0201; AGILE_PN: 150-79813; CAD_APPROVED: Yes; FPLIST: CC0201,CC0201_HD,0201_CC; HEIGHT: 0.33MM; MFG_NAME01: SAMSUNG; MFG_PN01: CL03C120JA3GNNC; Polyhex_Number: PD.005.0032; ROHS: Yes; Tolerance: 5%; VOLTAGE: 25V
C164 C165 = CAP_NP: CAP CER 18pF 50V 5% C0G 0201; CAD_APPROVED: Yes; HEIGHT: 0.35MM; MFG_NAME01: SAMSUNG; MFG_PN01: CL03C180JB3NNNH; Package Size: 0201; Package Type: 7” reel; Polyhex_Number: PD.005.0033; ROHS: Yes; Tolerance: 5%; VOLTAGE: 50V
QZ2 = XTAL: XTAL 32.768KHZ 12.5PF 20PPM 3.2X1.5MM SMT; AGILE_PN: 230-77653; CAD_APPROVED: Yes; HEIGHT: 0.9MM; MFG_NAME01: SEIKO EPSON; MFG_PN01: FC-135; Polyhex_Number: PD.018.0003; ROHS: Yes; Temp Range: -40C to +85C; Temp_Range: -40C to +85C; Tolerance: 20PPM
R28 = RES: RES MF 100K 1/16W 5% 0402; AGILE_PN: 470-75597; ASSY_OPT: DNP; CAD_APPROVED: Yes; FPLIST: RC0402_25,RC0402_HD,0402_CC; HEIGHT: 0.40 MM; MFG_NAME01: YAGEO; MFG_PN01: RC0402JR-07100KL; Polyhex_Number: PD.004.0004; ROHS: Yes; Temp Range: -55C to +155C; Temp_Range: -55C to +155C; Tolerance: 5%; VOLTAGE: 50V
R29 R30 = RES: RES MF 100K 1/16W 5% 0402; AGILE_PN: 470-75597; CAD_APPROVED: Yes; FPLIST: RC0402_25,RC0402_HD,0402_CC; HEIGHT: 0.40 MM; MFG_NAME01: YAGEO; MFG_PN01: RC0402JR-07100KL; Polyhex_Number: PD.004.0004; ROHS: Yes; Temp Range: -55C to +155C; Temp_Range: -55C to +155C; Tolerance: 5%; VOLTAGE: 50V
R35 = RES: RES MF 510K 1/16W 5% 0402; AGILE_PN: 470-76166; CAD_APPROVED: Yes; FPLIST: RC0402_25,RC0402_HD,0402_CC; HEIGHT: 0.4 MM; MFG_NAME01: YAGEO; MFG_PN01: RC0402JR-07510KL; Polyhex_Number: PD.004.0074; ROHS: Yes; Tolerance: 5%; VOLTAGE: 50V
R74 = RES: RES MF 4M7 OHM 1/20W 1% 0201; AGILE_PN: 470-81235; CAD_APPROVED: Yes; FPLIST: RC0201,0201_CC; HEIGHT: 0.26MM; MFG_NAME01: YAGEO; MFG_PN01: RC0201FR-074M7L; Polyhex_Number: PD.004.0221; ROHS: Yes; Temp Range: -55°C ~ 125C; Tolerance: 5%; VOLTAGE: 25V
Y1 = XTAL_13Y: XTAL 24MHZ 9pF -- SMT 3.2X2.5MM; AGILE_PN: 230-77392; CAD_APPROVED: Yes; HEIGHT: 0.60MM; MFG_NAME01: HOSONIC; MFG_PN01: E3SB24E000028E; Polyhex_Number: PD.018.0001; ROHS: Yes; Tolerance: 10PPM

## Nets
GND: C1.2 C2.2 C3.2 C5.2 C6.2 C7.2 C8.2 C10.2 C11.2 C12.2 C13.2 C14.2 C15.2 C16.2 C17.2 C18.2 C19.2 C20.2 C21.2 C22.2 C23.2 C24.2 C25.2 C27.2 C28.2 C29.2 C31.2 C32.2 C33.2 C34.2 C35.2 C36.2 C38.2 C39.2 C40.2 C41.2 C42.2 C43.2 C44.2 C45.2 C47.2 C48.2 C49.2 C50.2 C51.2 C53.2 C55.2 C56.2 C57.2 C58.2 C59.2 C60.2 C61.2 C62.2 C63.2 C64.2 C65.2 C67.2 C68.2 C69.2 C70.2 C71.2 C72.2 C80.2 C81.2 C83.2 C84.2 C85.2 C86.2 C87.2 C88.2 C89.2 C90.2 C91.2 C92.2 C93.2 C94.2 C95.2 C96.2 C97.2 C98.2 C99.2 C100.2 C101.2 C104.2 C106.2 C107.2 C108.2 C109.2 C164.2 C165.2 R1.2 R2.2 R3.2 R4.2 R5.2 R6.1 R24.2 R25.2 R26.2 R27.2 R31.2 R32.2 TP50.1(Pin1) U1.A1(VSS12) U1.A29(VSS46) U1.AA3(VSS49) U1.AA7(VSS50) U1.AA23(VSS47) U1.AA27(VSS48) U1.AB8(VSS59) U1.AB10(VSS51) U1.AB12(VSS52) U1.AB14(VSS53) U1.AB16(VSS54) U1.AB18(VSS56) U1.AB20(VSS57) U1.AB22(VSS58) U1.AC3(VSS62) U1.AC6(VSS63) U1.AC24(VSS60) U1.AC27(VSS61) U1.AE3(VSS65) U1.AE27(VSS64) U1.AG4(VSS76) U1.AG6(VSS78) U1.AG8(VSS79) U1.AG10(VSS67) U1.AG12(VSS68) U1.AG14(VSS69) U1.AG16(VSS70) U1.AG18(VSS71) U1.AG20(VSS72) U1.AG22(VSS73) U1.AG24(VSS74) U1.AG26(VSS75) U1.AJ1(VSS80) U1.AJ29(VSS81) U1.C4(VSS92) U1.C6(VSS93) U1.C8(VSS94) U1.C10(VSS82) U1.C12(VSS83) U1.C14(VSS84) U1.C16(VSS85) U1.C18(VSS86) U1.C20(VSS87) U1.C22(VSS89) U1.C24(VSS90) U1.C26(VSS91) U1.E3(VSS96) U1.E27(VSS95) U1.G3(VSS11) U1.G6(VSS98) U1.G24(VSS97) U1.G27(VSS10) U1.H8(VSS107) U1.H10(VSS100) U1.H12(VSS101) U1.H14(VSS102) U1.H16(VSS103) U1.H18(VSS104) U1.H20(VSS105) U1.H22(VSS106) U1.J3(VSS3) U1.J7(VSS4) U1.J23(VSS108) U1.J27(VSS109) U1.L3(VSS9) U1.L7(VSS1) U1.L14(VSS5) U1.L16(VSS6) U1.L23(VSS7) U1.L27(VSS8) U1.M11(VSS22) U1.M19(VSS33) U1.N3(VSS88) U1.N7(VSS99) U1.N11(VSS44) U1.N19(VSS55) U1.N23(VSS66) U1.N27(VSS77) U1.P11(VSS2) U1.P19(VSS13) U1.R3(VSS25) U1.R7(VSS26) U1.R11(VSS14) U1.R12(VSS15) U1.R13(VSS16) U1.R14(VSS17) U1.R16(VSS18) U1.R17(VSS19) U1.R18(VSS20) U1.R19(VSS21) U1.R23(VSS23) U1.R27(VSS24) U1.T11(VSS27) U1.T19(VSS28) U1.U3(VSS35) U1.U7(VSS36) U1.U11(VSS29) U1.U18(VSS30) U1.U19(VSS31) U1.U23(VSS32) U1.U27(VSS34) U1.V11(VSS37) U1.V19(VSS38) U1.W3(VSS43) U1.W7(VSS45) U1.W14(VSS39) U1.W16(VSS40) U1.W23(VSS41) U1.W27(VSS42) U2.A3(VSS) U2.A10(VSS) U2.AB3(VSS) U2.AB5(VSS) U2.AB8(VSS) U2.AB10(VSS) U2.C1(VSS) U2.C5(VSS) U2.C8(VSS) U2.C12(VSS) U2.D2(VSS) U2.D4(VSS) U2.D9(VSS) U2.D11(VSS) U2.E1(VSS) U2.E5(VSS) U2.E8(VSS) U2.E12(VSS) U2.G1(VSS) U2.G3(VSS) U2.G5(VSS) U2.G8(VSS) U2.G10(VSS) U2.G12(VSS) U2.J1(VSS) U2.J3(VSS) U2.J10(VSS) U2.J12(VSS) U2.K2(VSS) U2.K4(VSS) U2.K9(VSS) U2.K11(VSS) U2.N2(VSS) U2.N4(VSS) U2.N9(VSS) U2.N11(VSS) U2.P1(VSS) U2.P3(VSS) U2.P10(VSS) U2.P12(VSS) U2.T1(VSS) U2.T3(VSS) U2.T5(VSS) U2.T8(VSS) U2.T10(VSS) U2.T12(VSS) U2.V1(VSS) U2.V5(VSS) U2.V8(VSS) U2.V12(VSS) U2.W2(VSS) U2.W4(VSS) U2.W9(VSS) U2.W11(VSS) U2.Y1(VSS) U2.Y5(VSS) U2.Y8(VSS) U2.Y12(VSS) Y1.2 Y1.4 ; also on sheet 9 10 11 12 13 14 15 16 17 18 19 20 21 22 23 24 25 26 27
VDD_1V8: C1.1 C2.1 C3.1 C5.1 C6.1 C7.1 C8.1 C27.1 C80.1 C81.1 C83.1 C84.1 C85.1 C86.1 R13.1 R14.1 R15.1 R16.1 R17.1 R18.1 U1.AA11(NVCC_SAI2_SAI3_SPDIF) U1.AA16(PVCC2_1P8) U1.AA19(PVCC1_1P8) U1.AA24(NVCC_ENET) U1.J16(PVCC0_1P8) U1.K11(NVCC_JTAG) U1.R22(NVCC_CLK) U1.U22(NVCC_NAND) U1.U24(NVCC_SD1) U1.Y10(NVCC_I2C_UART) U2.F1(VDD1) U2.F12(VDD1) U2.G4(VDD1) U2.G9(VDD1) U2.T4(VDD1) U2.T9(VDD1) U2.U1(VDD1) U2.U12(VDD1) ; also on sheet 9 10 12 16 18 21 22 23 24 25 26 27
VDD_3V3: C18.1 C20.1 U1.AA14(NVCC_ECSPI_HDMI) U1.J11(NVCC_GPIO) U1.J14(VDD_USB_3P3) U1.Y11(NVCC_SAI1_SAI5) ; also on sheet 10 11 12 13 14 15 16 17 18 20 22 24 26 27
VDD_ARM: C13.1 C14.1 C15.1 C16.1 C17.1 C21.1 C22.1 C23.1 C24.1 C25.1 U1.T14(VDD_ARM_1) U1.T16(VDD_ARM_2) U1.U12(VDD_ARM_3) U1.U13(VDD_ARM_4) U1.U14(VDD_ARM_5) U1.U15(VDD_ARM_6) U1.U16(VDD_ARM_7) U1.U17(VDD_ARM_8) U1.V14(VDD_ARM_9) U1.V16(VDD_ARM_10) U1.W12(VDD_ARM_11) U1.W13(VDD_ARM_12) U1.W17(VDD_ARM_13) U1.Y14(VDD_ARM_14) U1.Y15(VDD_ARM_15) U1.Y16(VDD_ARM_16) ; also on sheet 10
VDD_MIPI_1V2_CAP: C72.1 U1.F20(VDD_MIPI_1P2_CAP)
VDD_SNVS_0V8: C11.1 U1.N26(VDD_SNVS_0P8_CAP)
VDD_SOC: C28.1 C29.1 C31.1 C32.1 C33.1 C34.1 C35.1 C36.1 C43.1 C44.1 C45.1 C47.1 C53.1 C55.1 C56.1 C57.1 C58.1 C59.1 C60.1 C61.1 TP49.1(Pin1) U1.K10(VDD_SOC_1) U1.K14(VDD_USB_0P8) U1.K15(VDD_PCI_0P8) U1.K16(VDD_MIPI_0P8) U1.L9(VDD_SOC_11) U1.L10(VDD_SOC_2) U1.L11(VDD_SOC_3) U1.L12(VDD_SOC_4) U1.L13(VDD_SOC_5) U1.L17(VDD_SOC_6) U1.L18(VDD_SOC_7) U1.L19(VDD_SOC_8) U1.L20(VDD_SOC_9) U1.L21(VDD_SOC_10) U1.M14(VDD_SOC_12) U1.M16(VDD_SOC_13) U1.N9(VDD_SOC_28) U1.N10(VDD_SOC_14) U1.N12(VDD_SOC_15) U1.N13(VDD_SOC_16) U1.N14(VDD_SOC_34) U1.N15(VDD_SOC_33) U1.N16(VDD_SOC_32) U1.N17(VDD_SOC_31) U1.N18(VDD_SOC_30) U1.N20(VDD_SOC_29) U1.N21(VDD_SOC_35) U1.P14(VDD_SOC_27) U1.P16(VDD_SOC_26) U1.R9(VDD_DRAM_PLL_0P8) U1.R10(VDD_SOC_25) U1.R20(VDD_SOC_24) U1.R21(VDD_ANA1_0P8) U1.U9(VDD_SOC_20) U1.U10(VDD_SOC_23) U1.U20(VDD_SOC_22) U1.U21(VDD_SAI_PLL_0P8) U1.W9(VDD_SOC_17) U1.W10(VDD_SOC_19) U1.W11(VDD_SOC_18) U1.W20(VDD_SOC_21) U1.W21(VDD_ARM_PLL_0P8) U1.W22(VDD_HDMI_0P8) ; also on sheet 10
VDDA_1V8: C12.1 C38.1 C39.1 C40.1 C41.1 C42.1 C48.1 C49.1 C50.1 C51.1 U1.AA20(VDD_EARC_1P8) U1.AA22(VDD_HDMI_1P8) U1.J19(VDD_USB_1P8) U1.J20(VDD_ANA0_1P8) U1.J22(VDD_LVDS_1P8) U1.K19(VDD_PCI_1P8) U1.K20(VDD_MIPI_1P8) U1.L22(VDD_24M_XTAL_1P8) U1.N22(VDD_ANA1_1P8) U1.R6(VDD_DRAM_PLL_1P8) U1.W18(VDD_SAI_PLL_1P8) U1.W19(VDD_AVPLL_1P8) U1.Y19(VDD_ARM_PLL_1P8) U1.Y20(VDD_ANA2_1P8) ; also on sheet 10
BOOT_MODE0: U1.G10(BOOT_MODE0) ; also on sheet 9
BOOT_MODE1: U1.F8(BOOT_MODE1) ; also on sheet 9
BOOT_MODE2: U1.G8(BOOT_MODE2) ; also on sheet 9
BOOT_MODE3: U1.G12(BOOT_MODE3) ; also on sheet 9
BT_WAKE_HOST: U1.AA28(SD1_DATA6) ; also on sheet 26
CAN1_RX: U1.AD18(SPDIF_RX) ; also on sheet 26
CAN1_TX: U1.AE18(SPDIF_TX) ; also on sheet 26
CLKIN1: TP13.1(Pin1) U1.K28(CLKIN1)
CLKIN2: TP14.1(Pin1) U1.L28(CLKIN2)
CLKOUT1: TP46.1(Pin1) U1.K29(CLKOUT1)
CLKOUT2: TP45.1(Pin1) U1.L29(CLKOUT2)
CSI1_CKN: U1.E22(MIPI_CSI1_CLK_N) ; also on sheet 25
CSI1_CKP: U1.D22(MIPI_CSI1_CLK_P) ; also on sheet 25
CSI1_DN0: U1.E18(MIPI_CSI1_D0_N) ; also on sheet 25
CSI1_DN1: U1.E20(MIPI_CSI1_D1_N) ; also on sheet 25
CSI1_DN2: U1.E24(MIPI_CSI1_D2_N) ; also on sheet 25
CSI1_DN3: U1.E26(MIPI_CSI1_D3_N) ; also on sheet 25
CSI1_DP0: U1.D18(MIPI_CSI1_D0_P) ; also on sheet 25
CSI1_DP1: U1.D20(MIPI_CSI1_D1_P) ; also on sheet 25
CSI1_DP2: U1.D24(MIPI_CSI1_D2_P) ; also on sheet 25
CSI1_DP3: U1.D26(MIPI_CSI1_D3_P) ; also on sheet 25
CSI2_CKN: U1.B23(MIPI_CSI2_CLK_N) ; also on sheet 25
CSI2_CKP: U1.A23(MIPI_CSI2_CLK_P) ; also on sheet 25
CSI2_DN0: U1.B25(MIPI_CSI2_D0_N) ; also on sheet 25
CSI2_DN1: U1.B24(MIPI_CSI2_D1_N) ; also on sheet 25
CSI2_DN2: U1.B22(MIPI_CSI2_D2_N) ; also on sheet 25
CSI2_DN3: U1.B21(MIPI_CSI2_D3_N) ; also on sheet 25
CSI2_DP0: U1.A25(MIPI_CSI2_D0_P) ; also on sheet 25
CSI2_DP1: U1.A24(MIPI_CSI2_D1_P) ; also on sheet 25
CSI2_DP2: U1.A22(MIPI_CSI2_D2_P) ; also on sheet 25
CSI2_DP3: U1.A21(MIPI_CSI2_D3_P) ; also on sheet 25
CSI_MCLK: U1.A4(GPIO1_IO14) ; also on sheet 25
DRAM_CA0_A: U1.L6(DRAM_AC08/CA0_A_/_A12) U2.R2(CA0_B)
DRAM_CA0_B: U1.W4(DRAM_AC28/CA0_B_/_A13) U2.H2(CA0_A)
DRAM_CA1_A: U1.L4(DRAM_AC09/CA1_A_/_A11) U2.P2(CA1_B)
DRAM_CA1_B: U1.W5(DRAM_AC29/CA1_B_/_BA0) U2.J2(CA1_A)
DRAM_CA2_A: U1.E4(DRAM_AC10/CA2_A_/_A7) U2.R9(CA2_B)
DRAM_CA2_B: U1.AE4(DRAM_AC30/CA2_B_/_A10(AP)) U2.H9(CA2_A)
DRAM_CA3_A: U1.D4(DRAM_AC11/CA3_A_/_A8) U2.R10(CA3_B)
DRAM_CA3_B: U1.AF4(DRAM_AC31/CA3_B_/_A0) U2.H10(CA3_A)
DRAM_CA4_A: U1.N4(DRAM_AC12/CA4_A_/_A6) U2.R11(CA4_B)
DRAM_CA4_B: U1.U5(DRAM_AC32/CA4_B_/_C2) U2.H11(CA4_A)
DRAM_CA5_A: U1.N5(DRAM_AC13/CA5_A_/_A5) U2.P11(CA5_B)
DRAM_CA5_B: U1.U6(DRAM_AC33/CA5_B/_CAS_n(A15)) U2.J11(CA5_A)
DRAM_CK_C_A: R9.2 U1.M2(DRAM_AC05/CK_c_A_/_BG1) U2.P9(CK_c_B)
DRAM_CK_C_B: R10.2 U1.V1(DRAM_AC25/CK_c_B_/_A1) U2.J9(CK_c_A)
DRAM_CK_T_A: R9.1 U1.M1(DRAM_AC04/CK_t_A_/_BG0) U2.P8(CK_t_B)
DRAM_CK_T_B: R10.1 U1.V2(DRAM_AC24/CK_t_B_/_A2) U2.J8(CK_t_A)
DRAM_CKE0_A: R3.1 U1.J6(DRAM_AC00/CKE0_A_/_CKE0) U2.P4(CKE0_B)
DRAM_CKE0_B: R1.1 U1.AA4(DRAM_AC20/CKE0_B_/_CK_t_B) U2.J4(CKE0_A)
DRAM_CKE1_A: R4.1 U1.G5(DRAM_AC01/CKE1_A_/_CKE1) U2.P5(CKE1_B)
DRAM_CKE1_B: R2.1 U1.AA5(DRAM_AC21/CKE1_B_/_CK_c_B) U2.J5(CKE1_A)
DRAM_DATA0_A: U1.B3(DRAM_DQ00) U2.AA11(DQ8_B)
DRAM_DATA0_B: U1.AC1(DRAM_DQ16) U2.B2(DQ0_A)
DRAM_DATA1_A: U1.A2(DRAM_DQ01) U2.Y11(DQ9_B)
DRAM_DATA1_B: U1.AB1(DRAM_DQ17) U2.C2(DQ1_A)
DRAM_DATA2_A: U1.E1(DRAM_DQ02) U2.V11(DQ10_B)
DRAM_DATA2_B: U1.W2(DRAM_DQ18) U2.F2(DQ3_A)
DRAM_DATA3_A: U1.F2(DRAM_DQ03) U2.U11(DQ11_B)
DRAM_DATA3_B: U1.Y2(DRAM_DQ19) U2.E2(DQ2_A)
DRAM_DATA4_A: U1.E2(DRAM_DQ04) U2.U9(DQ12_B)
DRAM_DATA4_B: U1.Y1(DRAM_DQ20) U2.E4(DQ5_A)
DRAM_DATA5_A: U1.C1(DRAM_DQ05) U2.V9(DQ13_B)
DRAM_DATA5_B: U1.W1(DRAM_DQ21) U2.F4(DQ4_A)
DRAM_DATA6_A: U1.C2(DRAM_DQ06) U2.Y9(DQ14_B)
DRAM_DATA6_B: U1.AC2(DRAM_DQ22) U2.B4(DQ7_A)
DRAM_DATA7_A: U1.B1(DRAM_DQ07) U2.AA9(DQ15_B)
DRAM_DATA7_B: TP23.1(Pin1) U1.AD1(DRAM_DQ23) U2.C4(DQ6_A)
DRAM_DATA8_A: U1.G1(DRAM_DQ08) U2.AA2(DQ0_B)
DRAM_DATA8_B: U1.AH3(DRAM_DQ24) U2.B11(DQ8_A)
DRAM_DATA9_A: U1.H1(DRAM_DQ09) U2.Y2(DQ1_B)
DRAM_DATA9_B: U1.AJ2(DRAM_DQ25) U2.C11(DQ9_A)
DRAM_DATA10_A: U1.K1(DRAM_DQ10) U2.V4(DQ5_B)
DRAM_DATA10_B: U1.AE1(DRAM_DQ26) U2.E11(DQ10_A)
DRAM_DATA11_A: U1.K2(DRAM_DQ11) U2.V2(DQ2_B)
DRAM_DATA11_B: U1.AD2(DRAM_DQ27) U2.F11(DQ11_A)
DRAM_DATA12_A: U1.L2(DRAM_DQ12) U2.U2(DQ3_B)
DRAM_DATA12_B: U1.AE2(DRAM_DQ28) U2.F9(DQ12_A)
DRAM_DATA13_A: U1.L1(DRAM_DQ13) U2.U4(DQ4_B)
DRAM_DATA13_B: U1.AG1(DRAM_DQ29) U2.E9(DQ13_A)
DRAM_DATA14_A: U1.G2(DRAM_DQ14) U2.AA4(DQ7_B)
DRAM_DATA14_B: U1.AG2(DRAM_DQ30) U2.C9(DQ14_A)
DRAM_DATA15_A: TP24.1(Pin1) U1.F1(DRAM_DQ15) U2.Y4(DQ6_B)
DRAM_DATA15_B: U1.AH1(DRAM_DQ31) U2.B9(DQ15_A)
DRAM_DMI0_A: U1.B2(DRAM_DM0) U2.Y10(DMI1_B)
DRAM_DMI0_B: U1.AB2(DRAM_DM2) U2.C3(DMI0_A)
DRAM_DMI1_A: U1.H2(DRAM_DM1) U2.Y3(DMI0_B)
DRAM_DMI1_B: U1.AH2(DRAM_DM3) U2.C10(DMI1_A)
DRAM_nCS0_A: U1.N6(DRAM_AC02/CS0_A_/_CS0_n) U2.R4(CS0_B)
DRAM_nCS0_B: U1.U4(DRAM_AC23/CS0_B_/_--) U2.H4(CS0_A)
DRAM_nCS1_A: U1.J4(DRAM_AC03/CS1_A_/_C0) U2.R3(CS1_B)
DRAM_nCS1_B: U1.AA6(DRAM_AC22/CS1_B_/_--) U2.H3(CS1_A)
DRAM_nRESET: R5.1 U1.T1(DRAM_RESET_N) U2.T11(RESET_N)
DRAM_SDQS0_C_A: U1.D1(DRAM_DQS0_N) U2.V10(DQS1_c_B)
DRAM_SDQS0_C_B: U1.AA1(DRAM_DQS2_N) U2.E3(DQS0_c_A)
DRAM_SDQS0_T_A: U1.D2(DRAM_DQS0_P) U2.W10(DQS1_t_B)
DRAM_SDQS0_T_B: U1.AA2(DRAM_DQS2_P) U2.D3(DQS0_t_A)
DRAM_SDQS1_C_A: U1.J1(DRAM_DQS1_N) U2.V3(DQS0_c_B)
DRAM_SDQS1_C_B: U1.AF1(DRAM_DQS3_N) U2.E10(DQS1_c_A)
DRAM_SDQS1_T_A: U1.J2(DRAM_DQS1_P) U2.W3(DQS0_t_B)
DRAM_SDQS1_T_B: U1.AF2(DRAM_DQS3_P) U2.D10(DQS1_t_A)
DRAM_VREF: TP1.1(Pin1) U1.R2(DRAM_VREF)
DRAM_ZQ0: R7.2 U2.A5(ZQ0)
DRAM_ZQ1: R8.2 U2.A8(ZQ1)
DSI_CKN: U1.B18(MIPI_DSI1_CLK_N) ; also on sheet 25
DSI_CKP: U1.A18(MIPI_DSI1_CLK_P) ; also on sheet 25
DSI_CTP_nINT: U1.AJ15(SAI2_MCLK) ; also on sheet 25
DSI_DN0: U1.B16(MIPI_DSI1_D0_N) ; also on sheet 25
DSI_DN1: U1.B17(MIPI_DSI1_D1_N) ; also on sheet 25
DSI_DN2: U1.B19(MIPI_DSI1_D2_N) ; also on sheet 25
DSI_DN3: U1.B20(MIPI_DSI1_D3_N) ; also on sheet 25
DSI_DP0: U1.A16(MIPI_DSI1_D0_P) ; also on sheet 25
DSI_DP1: U1.A17(MIPI_DSI1_D1_P) ; also on sheet 25
DSI_DP2: U1.A19(MIPI_DSI1_D2_P) ; also on sheet 25
DSI_DP3: U1.A20(MIPI_DSI1_D3_P) ; also on sheet 25
EARC_AUX: TP44.1(Pin1) U1.AH23(EARC_AUX)
EARC_N_HPD: U1.AH22(EARC_N_HPD) ; also on sheet 17
EARC_P_UTIL: U1.AJ23(EARC_P_UTIL) ; also on sheet 17
ECSPI2_MISO: U1.AH20(ECSPI2_MISO) ; also on sheet 27
ECSPI2_MOSI: U1.AJ21(ECSPI2_MOSI) ; also on sheet 27
ECSPI2_SCLK: U1.AH21(ECSPI2_SCLK) ; also on sheet 27
ECSPI2_SS0: U1.AJ22(ECSPI2_SS0) ; also on sheet 27
ENET1_MDC: U1.AH9(SAI1_RXD2) ; also on sheet 15
ENET1_MDIO: U1.AJ8(SAI1_RXD3) ; also on sheet 15
ENET1_nINT: U1.AF10(SAI1_RXD1) ; also on sheet 15
ENET1_nRST: U1.AC10(SAI1_RXD0) ; also on sheet 15
ENET1_RD0: U1.AD10(SAI1_RXD4) ; also on sheet 15
ENET1_RD1: U1.AE10(SAI1_RXD5) ; also on sheet 15
ENET1_RD2: U1.AH10(SAI1_RXD6) ; also on sheet 15
ENET1_RD3: U1.AH12(SAI1_RXD7) ; also on sheet 15
ENET1_RX_CTL: U1.AF12(SAI1_TXFS) ; also on sheet 15
ENET1_RXC: U1.AJ12(SAI1_TXC) ; also on sheet 15
ENET1_TD0: U1.AJ11(SAI1_TXD0) ; also on sheet 15
ENET1_TD1: U1.AJ10(SAI1_TXD1) ; also on sheet 15
ENET1_TD2: U1.AH11(SAI1_TXD2) ; also on sheet 15
ENET1_TD3: U1.AD12(SAI1_TXD3) ; also on sheet 15
ENET1_TX_CTL: U1.AH13(SAI1_TXD4) ; also on sheet 15
ENET1_TXC: U1.AH14(SAI1_TXD5) ; also on sheet 15
ENET_MDC: U1.AH28(ENET_MDC) ; also on sheet 16
ENET_MDIO: U1.AH29(ENET_MDIO) ; also on sheet 16
ENET_nINT: U1.AH17(SAI2_RXFS) ; also on sheet 26
ENET_nRST: U1.AJ16(SAI2_RXC) ; also on sheet 26
ENET_RD0: U1.AG29(ENET_RD0) ; also on sheet 16
ENET_RD1: U1.AG28(ENET_RD1) ; also on sheet 16
ENET_RD2: U1.AF29(ENET_RD2) ; also on sheet 16
ENET_RD3: U1.AF28(ENET_RD3) ; also on sheet 16
ENET_RX_CTL: U1.AE28(ENET_RX_CTL) ; also on sheet 16
ENET_RXC: U1.AE29(ENET_RXC) ; also on sheet 16
ENET_TD0: U1.AC25(ENET_TD0) ; also on sheet 16
ENET_TD1: U1.AE26(ENET_TD1) ; also on sheet 16
ENET_TD2: U1.AF26(ENET_TD2) ; also on sheet 16
ENET_TD3: U1.AD24(ENET_TD3) ; also on sheet 16
ENET_TX_CTL: U1.AF24(ENET_TX_CTL) ; also on sheet 16
ENET_TXC: U1.AE24(ENET_TXC) ; also on sheet 16
EXP_I2C3_nINT: U1.AC18(SPDIF_EXT_CLK) ; also on sheet 27
GPIO1_IO00: U1.A7(GPIO1_IO00) ; also on sheet 27
GPIO1_IO01: U1.E8(GPIO1_IO01) ; also on sheet 27
GPIO1_IO05: U1.B4(GPIO1_IO05) ; also on sheet 27
GPIO1_IO06: U1.A3(GPIO1_IO06) ; also on sheet 27
GPIO1_IO07: U1.F6(GPIO1_IO07) ; also on sheet 27
GPIO1_IO08: U1.A8(GPIO1_IO08) ; also on sheet 27
GPIO1_IO09: U1.B8(GPIO1_IO09) ; also on sheet 27
GPIO1_IO11: U1.D8(GPIO1_IO11) ; also on sheet 27
GPIO1_IO12: U1.A5(GPIO1_IO12) ; also on sheet 27
GPIO1_IO15: U1.B5(GPIO1_IO15) ; also on sheet 27
HDMI_CEC: U1.AD22(HDMI_CEC) ; also on sheet 17
HDMI_DDC_SCL: U1.AC22(HDMI_DDC_SCL) ; also on sheet 17
HDMI_DDC_SDA: U1.AF22(HDMI_DDC_SDA) ; also on sheet 17
HDMI_HPD: U1.AE22(HDMI_HPD) ; also on sheet 17
HDMI_TXCN: U1.AJ24(HDMI_TXC_N) ; also on sheet 17
HDMI_TXCP: U1.AH24(HDMI_TXC_P) ; also on sheet 17
HDMI_TXN0: U1.AJ25(HDMI_TX0_N) ; also on sheet 17
HDMI_TXN1: U1.AJ26(HDMI_TX1_N) ; also on sheet 17
HDMI_TXN2: U1.AJ27(HDMI_TX2_N) ; also on sheet 17
HDMI_TXP0: U1.AH25(HDMI_TX0_P) ; also on sheet 17
HDMI_TXP1: U1.AH26(HDMI_TX1_P) ; also on sheet 17
HDMI_TXP2: U1.AH27(HDMI_TX2_P) ; also on sheet 17
I2C1_SCL: R13.2 U1.AC8(I2C1_SCL) ; also on sheet 10 26
I2C1_SDA: R14.2 U1.AH7(I2C1_SDA) ; also on sheet 10 26
I2C2_SCL: R15.2 U1.AH6(I2C2_SCL) ; also on sheet 23 26
I2C2_SDA: R16.2 U1.AE8(I2C2_SDA) ; also on sheet 23 26
I2C3_SCL: R17.2 U1.AJ7(I2C3_SCL) ; also on sheet 18 19 26
I2C3_SDA: R18.2 U1.AJ6(I2C3_SDA) ; also on sheet 18 19 26
IOEXP0_nINT: U1.T28(NAND_READY_B) ; also on sheet 26
IOEXP1_nINT: U1.W26(SD1_STROBE) ; also on sheet 26
JTAG_MOD: R32.1 TP22.1(Pin1) U1.G20(JTAG_MOD) ; also on sheet 24
JTAG_TCK: R31.1 TP5.1(Pin1) U1.G18(JTAG_TCK) ; also on sheet 24
JTAG_TDI: TP3.1(Pin1) U1.G16(JTAG_TDI) ; also on sheet 24
JTAG_TDO: TP6.1(Pin1) U1.F14(JTAG_TDO) ; also on sheet 24
JTAG_TMS: TP4.1(Pin1) U1.G14(JTAG_TMS) ; also on sheet 24
LVDS0_BLT_PWM: U1.B7(GPIO1_IO10) ; also on sheet 20
LVDS0_CLK_N: U1.G28(LVDS0_CLK_N) ; also on sheet 20
LVDS0_CLK_P: U1.F29(LVDS0_CLK_P) ; also on sheet 20
LVDS0_CTP_nINT_1V8: U1.AJ19(SAI3_RXFS) ; also on sheet 26
LVDS0_TX0_N: U1.E28(LVDS0_D0_N) ; also on sheet 20
LVDS0_TX0_P: U1.D29(LVDS0_D0_P) ; also on sheet 20
LVDS0_TX1_N: U1.F28(LVDS0_D1_N) ; also on sheet 20
LVDS0_TX1_P: U1.E29(LVDS0_D1_P) ; also on sheet 20
LVDS0_TX2_N: U1.H28(LVDS0_D2_N) ; also on sheet 20
LVDS0_TX2_P: U1.G29(LVDS0_D2_P) ; also on sheet 20
LVDS0_TX3_N: U1.J28(LVDS0_D3_N) ; also on sheet 20
LVDS0_TX3_P: U1.H29(LVDS0_D3_P) ; also on sheet 20
LVDS1_BLT_PWM: U1.A6(GPIO1_IO13) ; also on sheet 20
LVDS1_CLK_N: U1.B28(LVDS1_CLK_N) ; also on sheet 20
LVDS1_CLK_P: U1.A28(LVDS1_CLK_P) ; also on sheet 20
LVDS1_CTP_nINT_1V8: U1.AJ18(SAI3_RXC) ; also on sheet 26
LVDS1_TX0_N: U1.B26(LVDS1_D0_N) ; also on sheet 20
LVDS1_TX0_P: U1.A26(LVDS1_D0_P) ; also on sheet 20
LVDS1_TX1_N: U1.B27(LVDS1_D1_N) ; also on sheet 20
LVDS1_TX1_P: U1.A27(LVDS1_D1_P) ; also on sheet 20
LVDS1_TX2_N: U1.C28(LVDS1_D2_N) ; also on sheet 20
LVDS1_TX2_P: U1.B29(LVDS1_D2_P) ; also on sheet 20
LVDS1_TX3_N: U1.D28(LVDS1_D3_N) ; also on sheet 20
LVDS1_TX3_P: U1.C29(LVDS1_D3_P) ; also on sheet 20
NVCC_DRAM_1V1: C62.1 C63.1 C64.1 C65.1 C67.1 C68.1 C69.1 C70.1 C71.1 C87.1 C88.1 C89.1 C90.1 C91.1 C92.1 C93.1 C94.1 C95.1 C96.1 C97.1 C98.1 C99.1 C100.1 C101.1 C104.1 R7.1 R8.1 U1.AA8(NVCC_DRAM_2) U1.AA10(NVCC_DRAM_1) U1.J8(NVCC_DRAM_4) U1.J10(NVCC_DRAM_3) U1.L8(NVCC_DRAM_5) U1.N8(NVCC_DRAM_6) U1.R8(NVCC_DRAM_7) U1.U8(NVCC_DRAM_8) U1.W8(NVCC_DRAM_9) U2.A4(VDD2) U2.A9(VDD2) U2.AA3(VDDQ) U2.AA5(VDDQ) U2.AA8(VDDQ) U2.AA10(VDDQ) U2.AB4(VDD2) U2.AB9(VDD2) U2.B3(VDDQ) U2.B5(VDDQ) U2.B8(VDDQ) U2.B10(VDDQ) U2.D1(VDDQ) U2.D5(VDDQ) U2.D8(VDDQ) U2.D12(VDDQ) U2.F3(VDDQ) U2.F5(VDD2) U2.F8(VDD2) U2.F10(VDDQ) U2.G2(ODT_CA_A) U2.H1(VDD2) U2.H5(VDD2) U2.H8(VDD2) U2.H12(VDD2) U2.K1(VDD2) U2.K3(VDD2) U2.K10(VDD2) U2.K12(VDD2) U2.N1(VDD2) U2.N3(VDD2) U2.N10(VDD2) U2.N12(VDD2) U2.R1(VDD2) U2.R5(VDD2) U2.R8(VDD2) U2.R12(VDD2) U2.T2(ODT_CA_B) U2.U3(VDDQ) U2.U5(VDD2) U2.U8(VDD2) U2.U10(VDDQ) U2.W1(VDDQ) U2.W5(VDDQ) U2.W8(VDDQ) U2.W12(VDDQ) ; also on sheet 10
NVCC_SD2: C19.1 R21.1 R22.1 R23.1 U1.W24(NVCC_SD2) ; also on sheet 10 13
NVCC_SNVS_1V8: C10.1 R28.1 R29.1 R30.1 U1.R24(NVCC_SNVS_1P8) ; also on sheet 10
ONOFF: R30.2 TP7.1(Pin1) U1.G22(ONOFF) ; also on sheet 27
PCIE_CLKN: U1.E16(PCIE_REF_PAD_CLK_N) ; also on sheet 26
PCIE_CLKP: U1.D16(PCIE_REF_PAD_CLK_P) ; also on sheet 26
PCIe_nCLKREQ: U1.AF8(I2C4_SCL) ; also on sheet 26
PCIe_nDIS: U1.U26(SD1_DATA4) ; also on sheet 26
PCIe_nRST: U1.AA29(SD1_DATA5) ; also on sheet 26
PCIe_nWAKE: U1.AD8(I2C4_SDA) ; also on sheet 26
PCIE_RESREF: R24.1 U1.F16(PCIE_RESREF)
PCIE_RXN: U1.B14(PCIE_RXN_N) ; also on sheet 26
PCIE_RXP: U1.A14(PCIE_RXN_P) ; also on sheet 26
PCIE_TXN: U1.B15(PCIE_TXN_N) ; also on sheet 26
PCIE_TXP: U1.A15(PCIE_TXN_P) ; also on sheet 26
PCM_CLK: U1.AH15(SAI2_TXC) ; also on sheet 26
PCM_IN: U1.AJ14(SAI2_RXD0) ; also on sheet 26
PCM_OUT: U1.AH16(SAI2_TXD0) ; also on sheet 26
PCM_SYNC: U1.AJ17(SAI2_TXFS) ; also on sheet 26
PMIC_nINT: U1.D6(GPIO1_IO03) ; also on sheet 10
PMIC_ON_REQ: R28.2 TP9.1(Pin1) U1.F22(PMIC_ON_REQ) ; also on sheet 10 11
PMIC_STBY_REQ: TP10.1(Pin1) U1.J24(PMIC_STBY_REQ) ; also on sheet 10
POR_B: R29.2 TP8.1(Pin1) U1.J29(POR_B) ; also on sheet 10 24 26
QSPIA_DATA0: U1.R25(NAND_DATA00) ; also on sheet 22
QSPIA_DATA1: U1.L25(NAND_DATA01) ; also on sheet 22
QSPIA_DATA2: U1.L24(NAND_DATA02) ; also on sheet 22
QSPIA_DATA3: U1.N24(NAND_DATA03) ; also on sheet 22
QSPIA_nSS0: U1.L26(NAND_CE0_B) ; also on sheet 22
QSPIA_SCLK: U1.N25(NAND_ALE) ; also on sheet 22
SAI1_MCLK: U1.AE12(SAI1_MCLK) ; also on sheet 27
SAI1_RXC: U1.AH8(SAI1_RXC) ; also on sheet 27
SAI1_RXFS: U1.AJ9(SAI1_RXFS) ; also on sheet 27
SAI3_MCLK: U1.AJ20(SAI3_MCLK) ; also on sheet 18
SAI3_RXD: U1.AF18(SAI3_RXD) ; also on sheet 18
SAI3_TXC: U1.AH19(SAI3_TXC) ; also on sheet 18
SAI3_TXD: U1.AH18(SAI3_TXD) ; also on sheet 18
SAI3_TXFS: U1.AC16(SAI3_TXFS) ; also on sheet 18
SAI5_MCLK: U1.AF14(SAI5_MCLK) ; also on sheet 27
SAI5_RXC: U1.AD14(SAI5_RXC) ; also on sheet 27
SAI5_RXD0: U1.AE16(SAI5_RXD0) ; also on sheet 27
SAI5_RXD1: U1.AD16(SAI5_RXD1) ; also on sheet 27
SAI5_RXD2: U1.AF16(SAI5_RXD2) ; also on sheet 27
SAI5_RXD3: U1.AE14(SAI5_RXD3) ; also on sheet 27
SAI5_RXFS: U1.AC14(SAI5_RXFS) ; also on sheet 27
SD1_CLK: U1.W28(SD1_CLK) ; also on sheet 26
SD1_CMD: U1.W29(SD1_CMD) ; also on sheet 26
SD1_DATA0: U1.Y29(SD1_DATA0) ; also on sheet 26
SD1_DATA1: U1.Y28(SD1_DATA1) ; also on sheet 26
SD1_DATA2: U1.V29(SD1_DATA2) ; also on sheet 26
SD1_DATA3: U1.V28(SD1_DATA3) ; also on sheet 26
SD2_CLK: U1.AB29(SD2_CLK) ; also on sheet 27
SD2_CMD: R22.2 U1.AB28(SD2_CMD) ; also on sheet 27
SD2_DATA0: R21.2 U1.AC28(SD2_DATA0) ; also on sheet 27
SD2_DATA1: U1.AC29(SD2_DATA1) ; also on sheet 27
SD2_DATA2: U1.AA26(SD2_DATA2) ; also on sheet 27
SD2_DATA3: U1.AA25(SD2_DATA3) ; also on sheet 27
SD2_nCD: U1.AD29(SD2_CD_B) ; also on sheet 27
SD2_RESET_B: R23.2 U1.AD28(SD2_RESET_B) ; also on sheet 10
SD2_VSEL: U1.E6(GPIO1_IO04) ; also on sheet 10
SD3_CLK: U1.U28(NAND_WE_B) ; also on sheet 22
SD3_CMD: U1.U29(NAND_WP_B) ; also on sheet 22
SD3_DATA0: U1.P29(NAND_DATA04) ; also on sheet 22
SD3_DATA1: U1.N29(NAND_DATA05) ; also on sheet 22
SD3_DATA2: U1.M29(NAND_DATA06) ; also on sheet 22
SD3_DATA3: U1.R29(NAND_DATA07) ; also on sheet 22
SD3_DATA4: U1.R28(NAND_RE_B) ; also on sheet 22
SD3_DATA5: U1.P28(NAND_CE2_B) ; also on sheet 22
SD3_DATA6: U1.N28(NAND_CE3_B) ; also on sheet 22
SD3_DATA7: U1.M28(NAND_CLE) ; also on sheet 22
SD3_STROBE: U1.T29(NAND_CE1_B) ; also on sheet 22
SD_nRST: U1.W25(SD1_RESET_B) ; also on sheet 26
SD_WAKE_HOST: U1.U25(SD1_DATA7) ; also on sheet 26
TCPC1_nINT: U1.AJ13(SAI1_TXD7) ; also on sheet 13
TCPC_nINT: U1.AC12(SAI1_TXD6) ; also on sheet 12
UART1_CTS: U1.AE6(UART3_RXD) ; also on sheet 26
UART1_RTS: U1.AJ4(UART3_TXD) ; also on sheet 26
UART1_RXD: U1.AD6(UART1_RXD) ; also on sheet 26
UART1_TXD: U1.AJ3(UART1_TXD) ; also on sheet 26
UART2_RXD: U1.AF6(UART2_RXD) ; also on sheet 24
UART2_TXD: U1.AH4(UART2_TXD) ; also on sheet 24
UART3_CTS: U1.AD20(ECSPI1_MISO) ; also on sheet 27
UART3_RTS: U1.AE20(ECSPI1_SS0) ; also on sheet 27
UART3_RXD: U1.AF20(ECSPI1_SCLK) ; also on sheet 27
UART3_TXD: U1.AC20(ECSPI1_MOSI) ; also on sheet 27
UART4_RXD: U1.AJ5(UART4_RXD) ; also on sheet 24
UART4_TXD: U1.AH5(UART4_TXD) ; also on sheet 24
USB1_DN: U1.E10(USB1_D_N) ; also on sheet 13
USB1_DP: U1.D10(USB1_D_P) ; also on sheet 13
USB1_RXN: U1.B9(USB1_RX_N) ; also on sheet 13
USB1_RXP: U1.A9(USB1_RX_P) ; also on sheet 13
USB1_SS_XSD: U1.AC26(SD2_WP) ; also on sheet 13
USB1_TXN: U1.B10(USB1_TX_N) ; also on sheet 13
USB1_TXP: U1.A10(USB1_TX_P) ; also on sheet 13
USB1_VBUS_3V3: U1.A11(USB1_VBUS) ; also on sheet 13
USB2_DN: U1.E14(USB2_D_N) ; also on sheet 14 23
USB2_DP: U1.D14(USB2_D_P) ; also on sheet 14 23
USB2_RXN: U1.B12(USB2_RX_N) ; also on sheet 14
USB2_RXP: U1.A12(USB2_RX_P) ; also on sheet 14
USB2_TXN: U1.B13(USB2_TX_N) ; also on sheet 14
USB2_TXP: U1.A13(USB2_TX_P) ; also on sheet 14
USB2_VBUS_3V3: U1.D12(USB2_VBUS) ; also on sheet 14
USER_KEY: U1.R26(NAND_DQS) ; also on sheet 27
WDOG_B: U1.B6(GPIO1_IO02) ; also on sheet 10
XTALI_24M: C108.1 R35.1 TP12.1(Pin1) U1.G25(XTALI_24M) Y1.3
XTALI_32K: C164.1 QZ2.2 R74.1 TP11.1(Pin1) U1.J25(RTC_XTALI)
XTALO_24M: C109.1 R35.2 U1.G26(XTALO_24M) Y1.1
XTALO_32K: C165.1 QZ2.1 R74.2 U1.J26(RTC_XTALO)
N109218202: R25.1 U1.F10(USB1_TXRTUNE)
N109218405: R26.1 U1.F12(USB2_TXRTUNE)
N109264586: R6.2 U1.R1(DRAM_ZN)
N109264594: TP2.1(Pin1) U1.P2(DRAM_AC19/MTEST_/_MTEST)
N109658046: R27.1 U1.AJ28(HDMI_REXT)
N110354220: C107.1 U1.F18(MIPI_VREG1_CAP)
N110354224: C106.1 U1.F24(MIPI_TEST_DNU)

Not connected (* = marked no-connect by the designer): U1 AC4(DRAM_AC37/--_/_ODT1)* AC5(DRAM_AC38/--_/_CS1_n)* B11(USB1_DNU)* E12(USB2_DNU)* G4(DRAM_AC06/--_/_ACT_n)* J5(DRAM_AC07/--_/_A9)* L5(DRAM_AC14/_--_/_A4)* N1(DRAM_AC16/--_/_CK_t_A)* N2(DRAM_AC17/--_/_CK_c_A)* P1(DRAM_AC26/--_/_BA1)* R4(DRAM_AC27/--_/_PARITY)* R5(DRAM_AC15/--_/_A3)* T2(DRAM_ALERT_N)* U1(DRAM_AC34/_--_/_WE_n(A14))* U2(DRAM_AC35/--_/_RAS_n(A16))* W6(DRAM_AC36/--_/_ODT0)*; U2 A1(DNU)* A2(DNU)* A11(DNU)* A12(DNU)* AA1(DNU)* AA12(DNU)* AB1(DNU)* AB2(DNU)* AB11(DNU)* AB12(DNU)* B1(DNU)* B12(DNU)* G11(NC)* K5(NC)* K8(NC)* N5(NC)* N8(NC)*

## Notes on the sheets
sheet 1
- FRDM-IMX8MPLUS
- (FRDM-IMX8MPLUS Development Board)
- Table of Content
- Revision History
- Page 1
- COVER
- Page 2
- BLOCK DIAGRAM
- Rev. Code
- Date
- By
- Description
- Page 3
- PWR TREE
- A1
- 2024-11-30
- Polyhex
- Initial version
- Page 4
- CPU PWR
- A2
- 2025-01-15
- Polyhex
- ENET2_AVDDL to ENET2_DVDDL
- 3.3V volage level for RST and INT
- Page 5
- LPDDR4
- HDMI_DDC_SCL, HDMI_DDC_SDA, HDMI_CEC, HDMI_HPD are 3.3V signals
- W2_UART_CTS and W2_UART_CTS are crossed
- Page 6
- CPU IO
- Delete U7/U8, Change power supply DCDC solution U105/U106/U107
- Delete U39, VCC_EXT_3V3 supply DSI&CAM_3V3
- Page 7
- CPU PHY
- The 40-pin EXP CN (J18) is the same as 8MP EVK
- TCPC_nINT and TCPC1_nINT are connected to SAI1_TXD6/TXD7
- Page 8
- CPU MISC
- Add  Power Switch
- Fan connector (J29) to a 2-pin 2mm connector
- Page 9
- eMMC/QSPI
- Add Net DEB_UART4_TX/DEB_UART4_RX
- Add U104/74AVC4TD245GU
- Page 10
- BOOT CFG
- B1
- 2025-04-21
- Polyhex
- Update U4 MFG_PN01 from "W25Q64JWSSIQ" to "W25Q256JWPIQ"
- Page 11
- PMIC
- Update U51 Value/MFG_PN01 from "TJA1051T/3" to "TJA1051T/3/2Z"
- Update U6 Value/MFG_PN01 from "PCA9450CHN" to "PCA9450CHNY"
- Page 12
- SYS PWR
- Update U58,U61 Value/MFG_PN01 from "NTS0104GU12" to "NTS0104GU12,115"
- Update U11,U20 Value/MFG_PN01 from "NX20P0407" to "NX20P0407UKAZ"
- Page 13
- USB PWR TYPE-C PD
- Update U14 Value/MFG_PN01 from "NX20P3483UK" to "NX20P3483UKAZ"
- Update J3 Value/MFG_PN01 from "HY-TC-101" to "5001-UPC079B-24R1-01"
- Page 14
- USB3.0 TYPE-C DRP
- Update SW6,SW7,SW8 Value/MFG_PN01 from "TS-A016_H3P5" to "TS-A016_H2P5"
- Update U9 Value from "NX20P5090UK" to "NX20P5090UKAZ"
- Page 15
- USB3.0 HOST
- Update U10,U15 Value from "PTN5110" to "PTN5110NHQZ"
- Update FB2,FB3,FB4,FB5,FB6,FB7,FB8,FB9,FB10,FB13,FB14,FB17,FB18 Value from "PZ3216D600" to "BLM15PX121SN1D"
- Page 16
- Giga Ethernet1 POE-PD
- Update U13 Value from "SGM8709YN5G" to "SGM8709YN5G/TR"
- Update U63 Value from "74AVC4T3144GU12" to "74AVC4T3144GU12X"
- Page 17
- Giga Ethernet2 TSN
- Update U62 Value from "74AVC8T245BQ" to "74AVC8T245BQ,118"
- Update D4,D5,D10,D15,D17,D18,D19,D21,D23,D29,D31 Value from "BAT54HT1" to "BAT54HT1G"
- Page 18
- LVDS0/1
- Update U18 Value from "CBTL02043ABQ" to "CBTL02043ABQ,115"
- Add Test Point TP185
- Page 19
- MIPI CSI1/CSI2/DSI
- Change J21 Pin3 Net to HP_J_R, Pin4 Net to HP_J_L
- Add R631, Q25, R632
- Page 20
- HDMI Display
- Page 21
- MicroSD/EXP/BUTTON/LED
- Page 22
- DEBUG/JTAG/CAN/RTC
- Page 23
- Audio CODEC
- Page 24
- IO-EXP/PCIE SDIO MUX
- Page 25
- M.2 KEY-M PCIe3.0
- Page 26
- M.2 KEY-E WIFI/BT
- Page 27
- WIFI/BT
- 1. Interrupted lines coded with the same letter or letter
      combinations are electrically connected.
- Preliminary - Subject to Change without Notice!
- 2. Device type number is for reference only. The number
      varies with the manufacturer.
- This board was designed for maximum flexibility in
  software  development and demonstrates multiple
  functions possible with i.MX processors. Although best
  design practices have been applied, some areas may
  not be suitable for a mass-production design.
- 3. Special signal usage:
- _B Denotes - Active-Low Signal
- <> or [] Denotes - Vectored Signals
- 4. Interpret diagram in accordance with American
  National Standards Institute specifications, current
  revision, with the exception of logic block symbology.
- NXP CONFIDENTIAL AND PROPRIETARY
sheet 2
- FRDM-IMX8MPLUS Block Diagram
- MIPI CSI1#
- MIPI CSI2#
- MIPI DSI
- LVDS x2
- HDMI2.0 with eARC
- FPC 22Pin 0.5mm
- FPC 22Pin 0.5mm
- FPC 22Pin 0.5mm
- 2x20Pin 2.0mm
- HDMI Type-A
- LANE x4
- LANE x4
- LANE x4
- LANE x4
- MIPI CSI1
- MIPI CSI2
- MIPI DSI
- LVDS x2
- HDMI2.0
- Dual Role
- USB TYPE-C
- Button
- PMIC
- USB3.0
- DRP
- POWER
- Reset
- NXP PCA9450CHN
- HOST
- USB3.0 TYPE-A
- USB3.0
- HOST
- Onboard
- DRAM
- RF ANT
- x32 bits
- WIFI&BT
- SAMSUNG LPDDR4 32Gb
  K4FBE3D4HM-MGCJ
- DRAM
- SDHC1/UART/PCM
- Resistance skip
- M.2 NGFF
- RF ANT
- KEY-E:WiFi/BT
- PCIE3.0
- Resistance skip
- M.2 NGFF
- i.MX8M Plus
- eMMC 5.1
- x8 bits
- KEY-M: 2280
- SAMSUNG 32GB
  KLMBG2JETD-B041
- SDHC3
- ARM CORTEX 4x A53 + M7
- Giga Ethernet
- RJ45x1(PoE Header)
- RGMII x2
- Motorcomm YT8521SH-CA
- RJ45x1
- CAN Trans
- MicroSD
- CAN x2
- NXP Header
- x4 bits
- SDHC2
- NXP TJA1051T/3
- 2x5Pin 2.54mm
- SD3.0 Support
- JTAG
- JTAG
- 2x5Pin 1.27mm
- 10 PIN Header
- Button
- ONOFF/GPIO
- ONOFF
- UART2(A53)
- DBG UART
- USB Type C
- UART2(M7)
- UART->USB CH342F
- Button
- RTC
- I2C
- User/GPIO
- PCF2131
- User defined
- SAI/I2C
- Pi Header
- GPIO/UART/SPI/SAI
- 1*RGB
- 2x20Pin 2.54mm
- HP&MIC
- 3.5mm POLE Headphone
- 3x User/GPIO
- User defined
- Audio Codec
- HSL
- CTIA Standard
- HSR
- GND
- MIC
- GPIO/SAI/I2C...
- WM8962BECSN/R
- SPK L&R
sheet 3
- FRDM-IMX8MPLUS Development Board
- PMIC: PCA9450C
- CPU: i.MX8M Plus
- SEQ
- REG
- TYP
- Max Capability(mA)
- SEQ
- PWR/Signal
- TYP
- Required(mA)
- 1
  2
  3
  4
  5
  6
  7
  8
  8
  9
  10
- LDO1
  RTC_CLK
  BUCK1/3
  BUCK2
  LDO3
  BUCK5
  BUCK6
  BUCK4
  MUXSW
  LDO5
  POR_B
- 1.8
  --
  0.85/0.95
  0.85/0.95/1.0
  1.8
  1.8
  1.1
  3.3
  3.3
  3.3/1.8
  --
- 10
  --
  6000
  3000
  300
  2000
  2000
  3000
  400
  150
  --
- 1
  2
  3
  4
  5
  6
  7
  8
  8
  9
  10
- NVCC_SNVS_1V8
  32K_INTERNAL
  VDD_SOC
  VDD_ARM
  VDDA_1V8
  VDD_1V8/NVCC_xxx
  NVCC_DRAM_1V1
  VDD_3V3/NVCC_xxx
  VSD_3V3
  NVCC_SD2
  POR_B
- 1.8
  --
  0.85/0.95
  0.85/0.95/1.0
  1.8
  1.8
  1.1
  3.3
  3.3
  3.3/1.8
  --
- 10
  --
  5000
  2200
  300
  NxCxVx(0.5xF)
  NxCxVx(0.5xF)
  NxCxVx(0.5xF)
  300
  10
  --
- USB C SNK PD
- VBUS_IN
- VSYS
- USB C
     PD
- DCDC BUCK
- PFS5600AMMATES
- 3A
- 12-20V
- VDD_5V
- 10A
- 1.8V
- 3A
- LPDDR4
- VDD_1V8
  VDD2/VDDQ
- QSPI
- VDD_1V8
- eMMC
- VDD_1V8
  VDD_3V3
- MicroSD Card
- VDD_1V8/3V3
- Giga Ethernet1
- VDD_3V3
- Giga Ethernet2
- VDD_1V8
  VDD_3V3
- RGB LED
- 5.0V/60mA
- 5.0V
- HDMI
- 3.3V/50mA
- 3.3V
  5.0V
- 5.0V/100mA
- 1.8V/1.0A
- LVDS0
- 1.8V
  3.3V
  5.0V
  12.0V
- 3.3V/1.0A
- 5.0V/1.0A
- DCDC BUCK
- 12V/1.5A
- MP2263GD
- 1.8V/1.0A
- LVDS1
- 3.3V/1.0A
- 1.8V
  3.3V
  5.0V
  12.0V
- 5.0V/1.0A
- 12V/1.5A
- EXP Header 2x20P
- 3.3V/1.0A
- 3.3V
  5.0V
- 5.0V/1.0A
- EXP  Header NXP
- 3.3V/1.0A
- 3.3V
  5.0V
- 5.0V/1.0A
- CAN
- 5.0V/500mA
- 5.0V
- USB C DRP
- 5.0V/3.0A
- 5.0V
- MIPI CSI1
- 3.3V
- DCDC BUCK
- 3.3V/500mA
- 3.3V
- REF8320
- 2A
- MIPI CSI2
- 3.3V/500mA
- 3.3V
- MIPI DSI
- 3.3V/1.0A
- 3.3V
- M.E KEY-M 2280
- 3.3V
- DCDC BUCK
- 3.3V/8.0A
- 3.3V
- MFS5600AMMA7ES
- 15A
- M.E KEY-E WIFI&BT
- 3.3V/2.0A
- 3.3V
- 5.0V
- 3A
- WIFI&BT OnBoard
- 1.8V/1.0A
- 1.8V
- 3.3V/2.0A
- 3.3V
- USB3.0 HOST
- 5.0V/2.0A
- 5.0V
- Audio
- 1.8V/500mA
- 1.8V
  5.0V
- 5.0V/1.0A
sheet 4
- i.MX8M Plus PWR
- 3.3V
- 3.3V
- 1.8V
- PMIC Sense Point
- 3.3V
- 1.8V
- 1.8V
- 1.8V/3.3V
- PMIC Sense Point
sheet 5
- LPDDR4 4GB
- Power supply voltage sequence:
  RESET_n is held LOW.
  VDD1 >= VDD2
  VDD2 >= VDDQ
- Note:
- LPDDR4 ODT on i.MX 8M Plus is command-based, ODT_CA_A/B of LPDDR4 part should be connected directly to VDD2.
- Data Bus
- Command/Address
- Pin Name
- LPDDR4
- DDR4
- Pin Name
- LPDDR4
- DDR4
- DRAM_DQS0_P
  DRAM_DQS0_N
  DRAM_DM0
  DRAM_DQ00
  DRAM_DQ01
  DRAM_DQ02
  DRAM_DQ03
  DRAM_DQ04
  DRAM_DQ05
  DRAM_DQ06
  DRAM_DQ07
  DRAM_DQS1_P
  DRAM_DQS1_N
  DRAM_DM1
  DRAM_DQ08
  DRAM_DQ09
  DRAM_DQ10
  DRAM_DQ11
  DRAM_DQ12
  DRAM_DQ13
  DRAM_DQ14
  DRAM_DQ15
  DRAM_DQS2_P
  DRAM_DQS2_N
  DRAM_DM2
  DRAM_DQ16
  DRAM_DQ17
  DRAM_DQ18
  DRAM_DQ19
  DRAM_DQ20
  DRAM_DQ21
  DRAM_DQ22
  DRAM_DQ23
  DRAM_DQS3_P
  DRAM_DQS3_N
  DRAM_DM3
  DRAM_DQ24
  DRAM_DQ25
  DRAM_DQ26
  DRAM_DQ27
  DRAM_DQ28
  DRAM_DQ29
  DRAM_DQ30
  DRAM_DQ31
- DQS0_t_A
  DQS0_c_A
  DMI0_A
  DQ0_A
  DQ1_A
  DQ2_A
  DQ3_A
  DQ4_A
  DQ5_A
  DQ6_A
  DQ7_A
  DQS1_t_A
  DQS1_c_A
  DMI1_A
  DQ08_A
  DQ09_A
  DQ10_A
  DQ11_A
  DQ12_A
  DQ13_A
  DQ14_A
  DQ15_A
  DQS0_t_B
  DQS0_c_B
  DMI0_B
  DQ0_B
  DQ1_B
  DQ2_B
  DQ3_B
  DQ4_B
  DQ5_B
  DQ6_B
  DQ7_B
  DQS1_t_B
  DQS1_c_B
  DMI1_B
  DQ08_B
  DQ09_B
  DQ10_B
  DQ11_B
  DQ12_B
  DQ13_B
  DQ14_B
  DQ15_B
- DQSL_t_A
  DQSL_c_A
  DML_n_A / DBIL_n_A
  DQL0_A
  DQL1_A
  DQL2_A
  DQL3_A
  DQL4_A
  DQL5_A
  DQL6_A
  DQL7_A
  DQSU_t_A
  DQSU_c_A
  DMU_n_A / DBIU_n_A
  DQU0_A
  DQU1_A
  DQU2_A
  DQU3_A
  DQU4_A
  DQU5_A
  DQU6_A
  DQU7_A
  DQSL_t_B
  DQSL_c_B
  DML_n_B / DBIL_n_B
  DQL0_B
  DQL1_B
  DQL2_B
  DQL3_B
  DQL4_B
  DQL5_B
  DQL6_B
  DQL7_B
  DQSU_t_B
  DQSU_c_B
  DMU_n_B / DBIU_n_B
  DQU0_B
  DQU1_B
  DQU2_B
  DQU3_B
  DQU4_B
  DQU5_B
  DQU6_B
  DQU7_B
- DRAM_RESET_N
  DRAM_ALERT_N
  DRAM_AC00
  DRAM_AC01
  DRAM_AC02
  DRAM_AC03
  DRAM_AC04
  DRAM_AC05
  DRAM_AC06
  DRAM_AC07
  DRAM_AC08
  DRAM_AC09
  DRAM_AC10
  DRAM_AC11
  DRAM_AC12
  DRAM_AC13
  DRAM_AC14
  DRAM_AC15
  DRAM_AC16
  DRAM_AC17
  DRAM_AC19
  DRAM_AC20
  DRAM_AC21
  DRAM_AC22
  DRAM_AC23
  DRAM_AC24
  DRAM_AC25
  DRAM_AC26
  DRAM_AC27
  DRAM_AC28
  DRAM_AC29
  DRAM_AC30
  DRAM_AC31
  DRAM_AC32
  DRAM_AC33
  DRAM_AC34
  DRAM_AC35
  DRAM_AC36
  DRAM_AC37
  DRAM_AC38
  DRAM_ZN
  DRAM_VREF
- RESET_N
  MTEST1
  CKE0_A
  CKE1_A
  CS0_A
  CS1_A
  CK_t_A
  CK_c_A
  /
  /
  CA0_A
  CA1_A
  CA2_A
  CA3_A
  CA4_A
  CA5_A
  /
  /
  /
  /
  MTEST
  CKE0_B
  CKE1_B
  CS1_B
  CS0_B
  CK_t_B
  CK_c_B
  /
  /
  CA0_B
  CA1_B
  CA2_B
  CA3_B
  CA4_B
  CA5_B
  /
  /
  /
  /
  /
  ZQ
  VREF
- RESET_n
  ALERT_n / MTEST1
  CKE0
  CKE1
  CS0_n
  C0
  BG0
  BG1
  ACT_n
  A9
  A12
  A11
  A7
  A8
  A6
  A5
  A4
  A3
  CK_t_A
  CK_c_A
  MTEST
  CK_t_B
  CK_c_B
  /
  /
  A2
  A1
  BA1
  PARITY
  A13
  BA0
  A10 / AP
  A0
  C2
  CAS_n / A15
  WE_n / A14
  RAS_n / A16
  ODT0
  ODT1
  CS1_n
  ZQ
  VREF
sheet 6
- i.MX8M Plus IO Interface
- SAI2 to M.2
- SAI3 to Audio Codec
- 1.8V
- 1.8V
- 3.3V
- BT
- A53 Debug
- 3.3V
- BT
- M7 Debug
- 1.8V
- 1.8V
- PWM3
- 3.3V
- PWM2
- CLKO1
- CLKO2
- 1.8V
- 1.8V
- External PU is necessary for SD2_RESET_B to enable SD card power as default!
sheet 7
- i.MX8M Plus PHYs
- VBUS Voltage Range:0~3.3V
- VBUS Voltage Range:0~3.3V
- Note:
- MIPI_TEST_DNU is for internal test, can be floating for normal use.
- Note:
- 1. USB1_DNU, USB2_DNU are not functional, if USB ID function is needed, use common GPIO.
- 2. If USB connector is MicroAB or MicroB, USBx_VBUS MUST not connect directly to the 5V VBUS voltage
  of connector; Instead, this pin must be isloated with an external 30K 1% resistor.
sheet 8
- i.MX8M Plus MISC
- JTAG Debug
- # System On/Off Button
- PU
- PU
- PD
- PU
- PU
- PU
- PD
- Caution:
- BOOT_MODE0, BOOT_MODE1, BOOT_MODE2, BOOT_MODE3, JTAG_MOD and POR_B must be
  pulled to "111111" for i.MX8M Plus to enter Boundary Scan mode.
